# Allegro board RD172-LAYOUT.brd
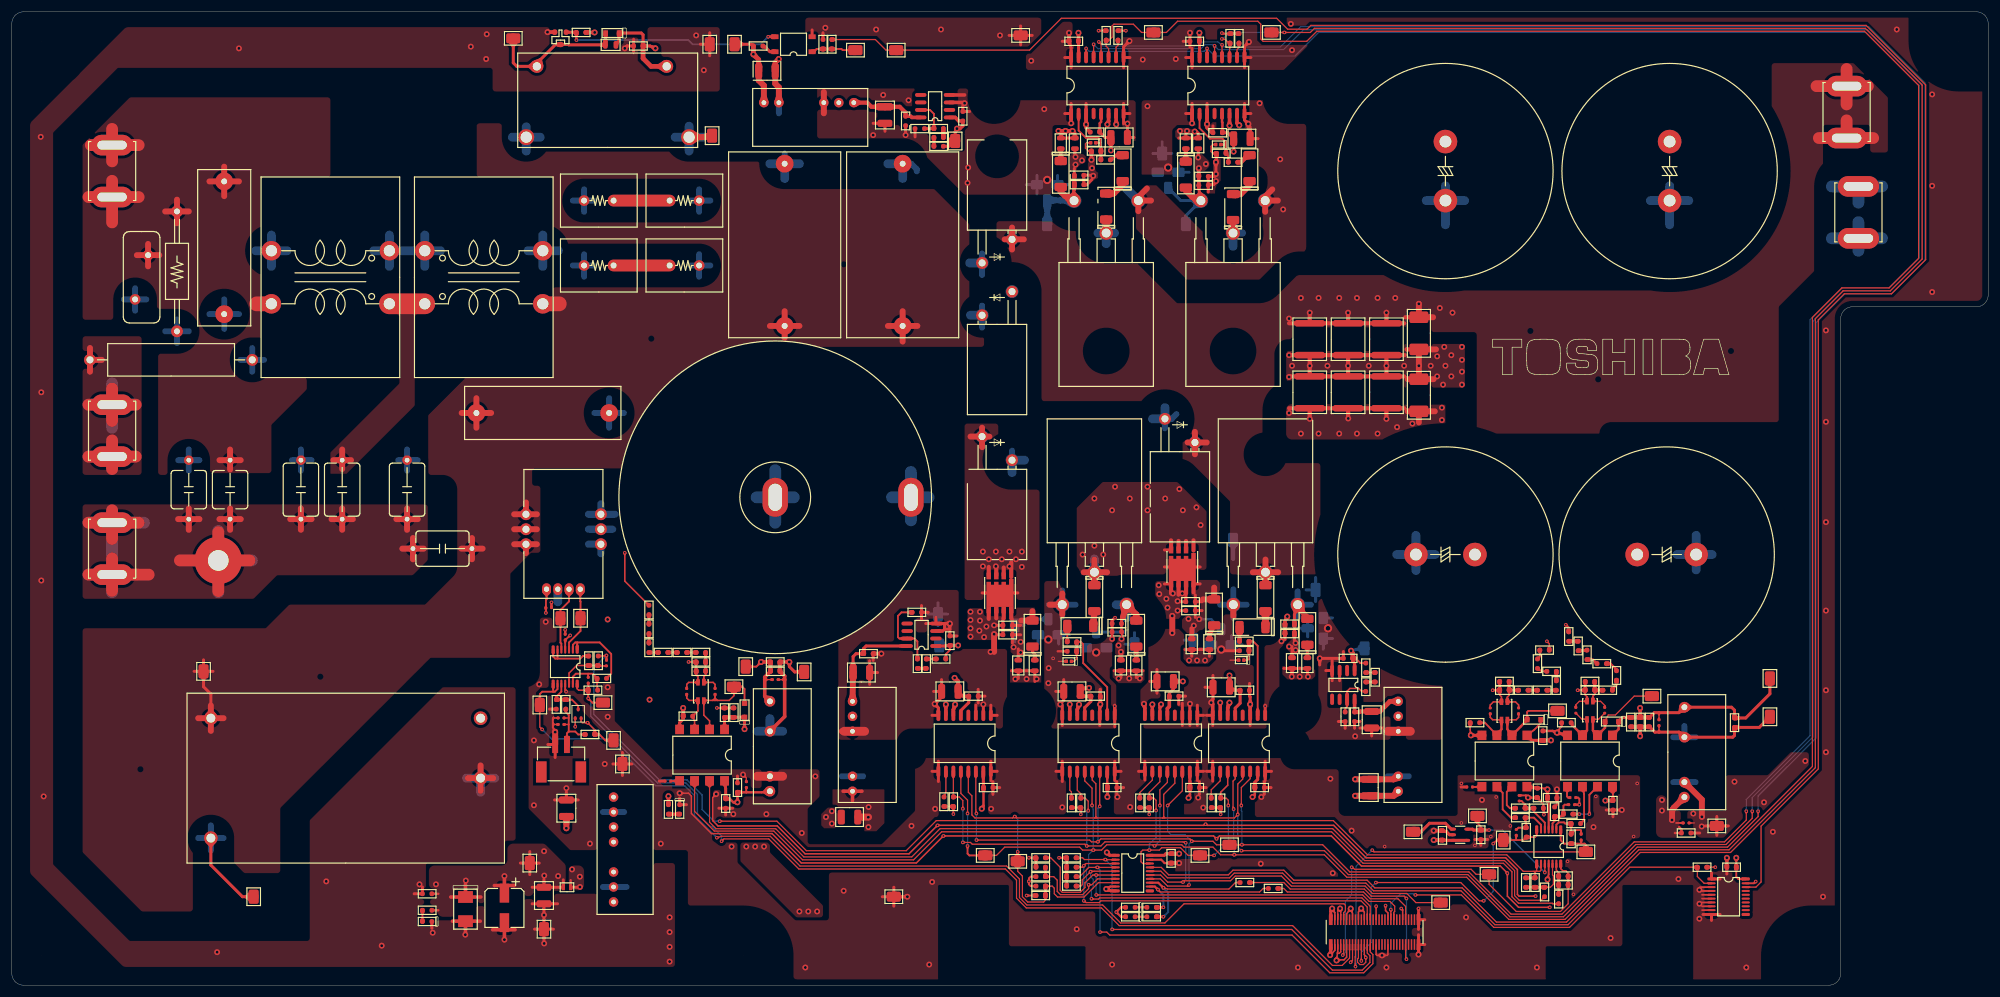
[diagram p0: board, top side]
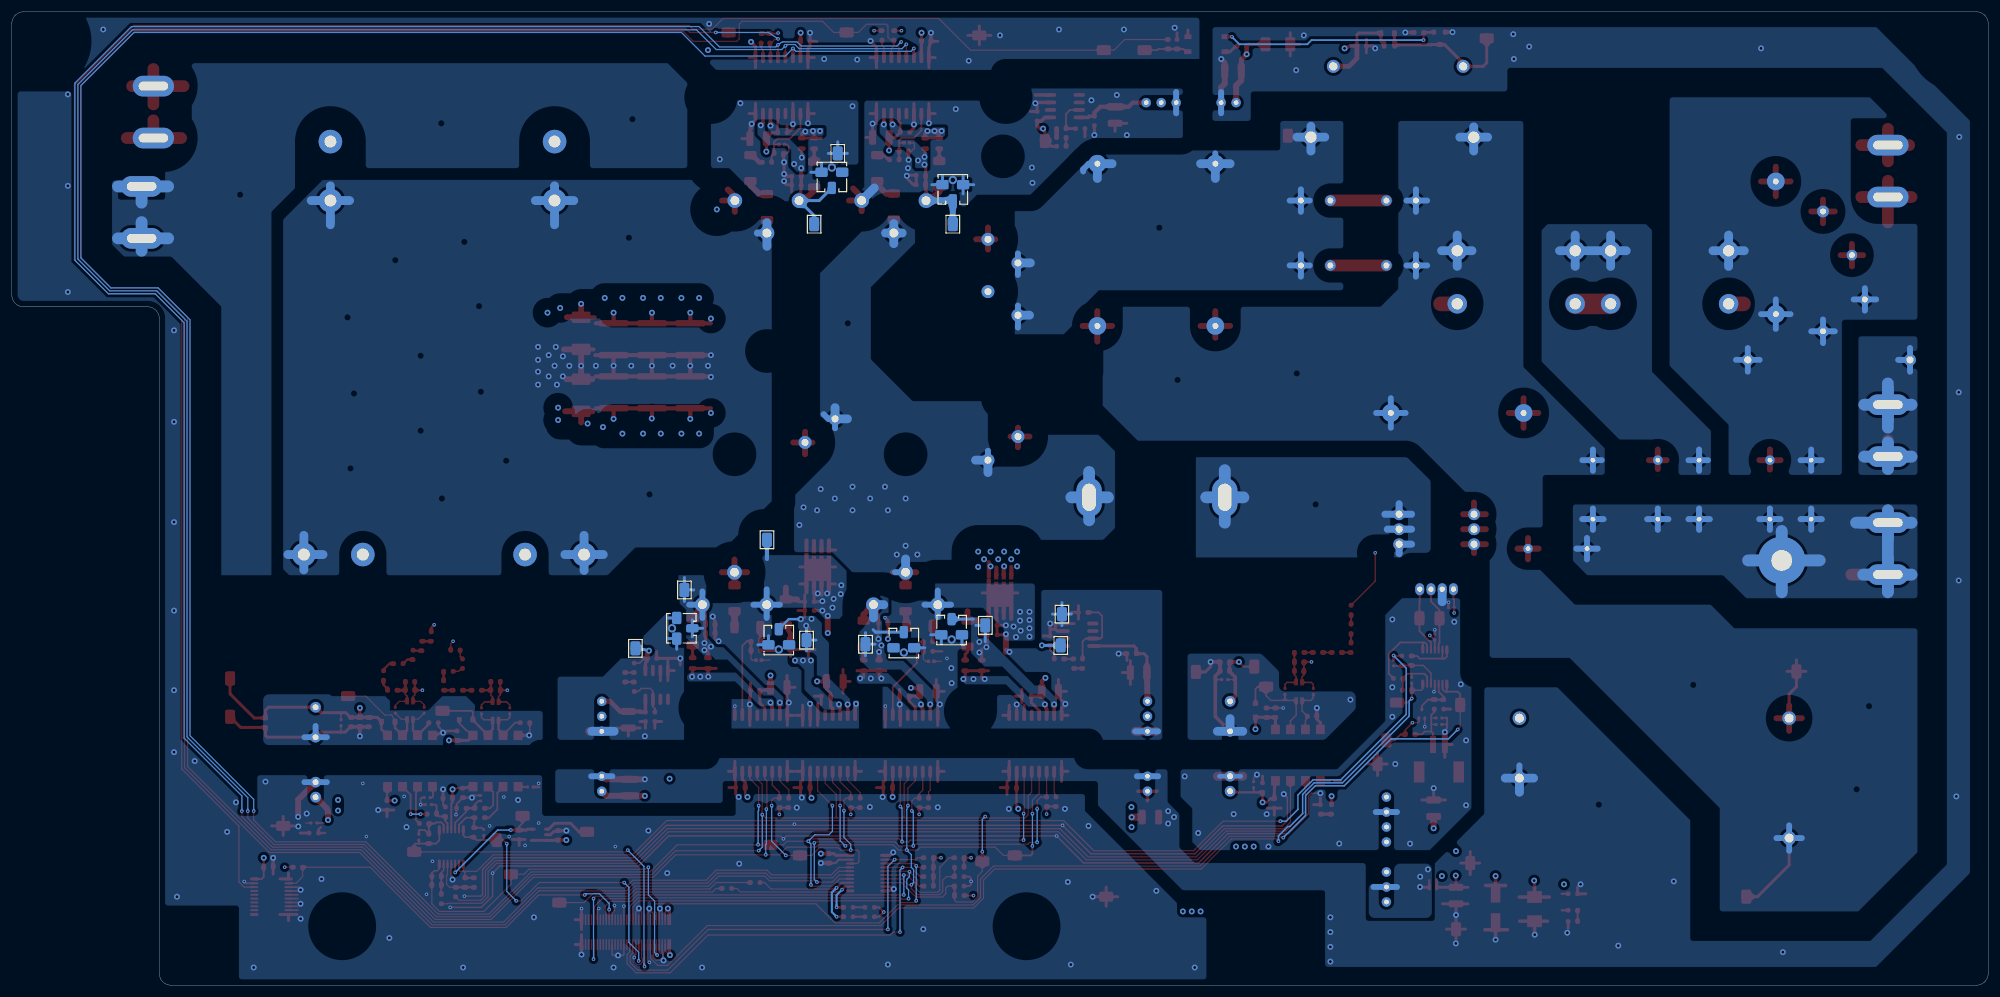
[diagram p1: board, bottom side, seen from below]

Outline 335 x 165 mm; copper layers: TOP, CONDUCTIVE2, CONDUCTIVE3, BOTTOM. Coordinates in mm from the lower left corner of the outline.
Outline path: 0,163 0.03,163.35 0.12,163.68 0.27,164 0.47,164.29 0.71,164.53 1,164.73 1.32,164.88 1.65,164.97 2,165 333,165 333.35,164.97 333.68,164.88 334,164.73 334.29,164.53 334.53,164.29 334.73,164 334.88,163.68 334.97,163.35 335,163 335,117 334.97,116.65 334.88,116.32 334.73,116 334.53,115.71 334.29,115.47 334,115.27 333.68,115.12 333.35,115.03 333,115 312,115 311.65,114.97 311.32,114.88 311,114.73 310.71,114.53 310.47,114.29 310.27,114 310.12,113.68 310.03,113.35 310,113 310,2 309.97,1.65 309.88,1.32 309.73,1 309.53,0.71 309.29,0.47 309,0.27 308.68,0.12 308.35,0.03 308,0 2,0 1.65,0.03 1.32,0.12 1,0.27 0.71,0.47 0.47,0.71 0.27,1 0.12,1.32 0.03,1.65 0,2 0,163

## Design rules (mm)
constraint set DEFAULT: 

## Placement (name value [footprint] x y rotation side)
C2  -  [_C_D_E22_5D0_8W9H18L_1]  36 125 90 top
C3  -  [_C_D_E22_5D0_8W9H18L_1]  90 97 180 top
C4  -  [C_S_1608]  106.2 159.2 180 top
C6  -  [_C_D_E27_5D0_8W19_0H_1]  151 125.5 270 top
C7  -  [_C_D_E27_5D0_8W19_0H_1]  131 125.5 270 top
C8  -  [C_D_10_0_CD45_D9_0_T_1]  49 84 270 top
C9  -  [C_D_10_0_CD45_D9_0_T_1]  56 84 270 top
C10  -  [C_S_1608]  70.4 15.5 180 top
C11  -  [CA_S_D6_3_L7_7_D8_PA_1]  83.5 13.1 270 top
C14  -  [C_S_1608]  211.5 33.5 0 top
C15  -  [C_S_3225]  205 50.5 180 top
C16  -  [C_S_1608]  209 50 0 top
C17  -  [C_S_3225]  230 33.5 90 top
C18  -  [C_S_3225]  230.5 45 270 top
C19  -  [C_S_1608]  227.6 45.5 270 top
C20  -  [C_S_1608]  208.9 56.7 180 top
C21  -  [C_S_1608]  226.5 55.4 180 top
C22  -  [C_S_1608]  216.6 61.2 180 top
C23  -  [C_S_1608]  200.5 33.5 0 top
C24  -  [C_S_3225]  195.5 51.5 180 top
C25  -  [C_S_1608]  197 49 0 top
C26  -  [C_S_1608]  199.8 65 0 top
C31  -  [C_S_1608]  186.5 33.5 0 top
C32  -  [C_S_3225]  179.7 49.8 180 top
C33  -  [C_S_1608]  183.7 49 0 top
C34  -  [C_S_1608]  187.3 61.3 180 top
C35  -  [C_S_3225]  142 28.5 180 top
C36  -  [C_S_3225]  144 53 0 top
C37  -  [C_S_1608]  145.2 56.2 0 top
C38  -  [C_S_1608]  159 58.4 90 top
C39  -  [C_S_1608]  179.7 56.6 180 top
C40  -  [C_S_1608]  165.5 33.5 0 top
C41  -  [C_S_3225]  159 49.8 180 top
C42  -  [C_S_1608]  163 49 0 top
C43  -  [C_S_1608]  168.8 61 0 top
C48  -  [CA_D_D35_L35_P10_CE6_1]  243 138 270 top
C49  -  [CA_D_D35_L35_P10_CE6_1]  281 138 270 top
C50  -  [C_S_3225]  128 155 0 top
C51  -  [C_S_3225]  148 147.5 270 top
C52  -  [C_S_1608]  151.5 146.5 270 top
C53  -  [C_S_1608]  161.2 147.3 90 top
C54  -  [CA_D_D35_L35_P10_CE6_1]  243 73 0 top
C55  -  [CA_D_D35_L35_P10_CE6_1]  280.5 73 180 top
C56  -  [C_S_1608]  180 160 180 top
C57  -  [C_S_3225]  187.7 143.7 0 top
C58  -  [C_S_1608]  183.6 144.6 180 top
C59  -  [C_S_1608]  180.9 135.7 0 top
C60  -  [C_S_1608]  183.8 141.4 180 top
C65  -  [C_S_1608]  200.5 160 180 top
C66  -  [C_S_3225]  208.5 143.5 0 top
C67  -  [C_S_1608]  204.4 144.5 180 top
C68  -  [C_S_1608]  202 135.6 180 top
C69  -  [C_S_1608]  205 141 180 top
C70  -  [C_S_1005]  97.7 51.7 270 top
C71  -  [C_S_1005]  91 64 0 top
C72  -  [C_S_1005]  93.8 59 90 top
C73  -  [C_S_1005]  100.8 54.6 90 top
C74  -  [C_S_1608]  92.3 47.6 270 top
C75  -  [C_S_1005]  93.1 45.3 180 top
C76  -  [C_S_3225]  90.2 15.2 270 top
C77  -  [C_S_3225]  94 30 90 top
C78  -  [C_S_1608]  249 25.5 270 top
C79  -  [C_S_1608]  242.5 25.4 90 top
C80  -  [C_S_1608]  129.4 53.2 0 top
C81  -  [C_S_1608]  129.4 54.8 0 top
C82  -  [C_S_1005]  129.4 51.8 0 top
C83  -  [C_S_1005]  124.5 34 90 top
C84  -  [C_S_1608]  123 33.5 90 top
C85  -  [C_S_1608]  120.8 46.2 90 top
C86  -  [C_S_1608]  121 30.8 270 top
C87  -  [C_S_1608]  116.8 54.8 180 top
C88  -  [C_S_1608]  263 18.5 0 top
C89  -  [C_S_1608]  256.6 17.4 270 top
C90  -  [C_S_1608]  274.4 44.6 270 top
C91  -  [C_S_1608]  271.4 30.5 270 top
C92  -  [C_S_1608]  261.1 31.8 0 top
C93  -  [C_S_1608]  267.5 50 180 top
C94  -  [C_S_1005]  266 25.1 270 top
C95  -  [C_S_1005]  264.4 30.6 180 top
C96  -  [C_S_1608]  259.5 42.3 90 top
C97  -  [C_S_1005]  255 25.9 270 top
C98  -  [C_S_1608]  258.6 32.6 270 top
C99  -  [C_S_1608]  253 50 180 top
C100  -  [C_S_1005]  255.5 31.7 270 top
C101  -  [C_S_1608]  276 44.6 270 top
C102  -  [C_S_1608]  277.6 44.6 270 top
C103  -  [C_S_1005]  279.2 44.5 270 top
C104  -  [C_S_1005]  283.8 27.5 0 top
C105  -  [C_S_1608]  283.8 25.8 0 top
C106  -  [C_S_1608]  196.5 21.5 270 top
C107  -  [C_S_1608]  174.4 18.4 180 top
C108  -  [C_S_1608]  174.4 16.8 180 top
C109  -  [C_S_1608]  291.5 20 180 top
C110  -  [C_S_5750_T2_5]  220 109.5 270 top
C111  -  [C_S_5750_T2_5]  220 100.5 270 top
C112  -  [C_S_5750_T2_5]  233 109.5 270 top
C113  -  [C_S_5750_T2_5]  233 100.5 270 top
C114  -  [C_S_5750_T2_5]  226.5 109.5 270 top
C115  -  [C_S_5750_T2_5]  226.5 100.5 270 top
C120  -  [C_D_10_0_CD45_D9_0_T_1]  67 84 270 top
C121  -  [C_D_10_0_CD45_D9_0_T_1]  73 74 180 top
C122  -  [_C_D_10_0_CD45_D6_5__1]  30 84 270 top
C123  -  [_C_D_10_0_CD45_D6_5__1]  37 84 270 top
CAM1  -  [_TH3_5_8_0]  35 72 0 top
CN1  -  [CN_S_6_1460820_X]  221.5 60.5 180 bottom
CN2  -  [CN_S_6_1460820_X]  205 58.5 90 bottom
CN3  -  [CN_S_6_1460820_X]  183.8 58 90 bottom
CN4  -  [CN_S_6_1460820_X]  175.7 60.2 90 bottom
CN5  -  [CN_S_6_1460820_X]  175.5 134.9 270 bottom
CN6  -  [CN_S_6_1460820_X]  196 137 270 bottom
CN7  -  [CN_S_BM02B_PASS_TFT__1]  93.1 37.5 0 top
CN8  -  [CN_S_WR_60S_VFH05_N1]  231 9 0 top
CT1  -  [_CT_D_F02PXXXS05L_PI_1]  93.5 76.5 90 top
D2  -  [D_S_1_1E1A_USC_AC]  101.8 161.4 0 top
D4  -  [_D_S_M_FLAT_3_4E1A_A_1]  210.3 60.7 0 top
D5  -  [_D_S_M_FLAT_3_4E1A_A_1]  219.6 59.9 270 top
D6  -  [_D_D_TO_220_2L_2_10A_1]  198 92 180 top
D7  -  [_D_D_TO_220_2L_2_10A_1#2]  167 126.43 0 top
D8  -  [_D_S_SOD_882_CST2_1__1]  208.4 55.1 0 top
D9  -  [_D_S_M_FLAT_3_4E1A_A_1]  203.8 63.2 270 top
D10  -  [_D_S_M_FLAT_3_4E1A_A_1]  181.1 60.9 0 top
D11  -  [_D_S_M_FLAT_3_4E1A_A_1]  190.6 59.6 270 top
D12  -  [_D_D_TO_220_2L_2_10A_1#2]  167 113.57 180 top
D13  -  [_D_S_SOD_882_CST2_1__1]  179.18 54.9 0 top
D14  -  [_D_D_TO_220_2L_2_10A_1]  167 89 180 top
D15  -  [_D_S_M_FLAT_3_4E1A_A_1]  173 59.6 270 top
D16  -  [_D_S_M_FLAT_3_4E1A_A_1]  188.3 138.5 270 top
D17  -  [_D_S_M_FLAT_3_4E1A_A_1]  177.8 137.5 90 top
D18  -  [_D_S_SOD_882_CST2_1__1]  183.3 142.8 0 top
D19  -  [_D_S_M_FLAT_3_4E1A_A_1]  199 137.4 90 top
D20  -  [_D_S_SOD_882_CST2_1__1]  204.5 142.5 0 top
D21  -  [_D_S_M_FLAT_3_4E1A_A_1]  209.8 138.5 270 top
D22  -  [_D_S_EMD3_SOT_416_SC_1]  96 46 90 top
D23  -  [D_S_1_1E1A_USC_AC]  124.2 46.6 270 top
D24  -  [D_S_1_1E1A_USC_AC]  271.2 44.7 0 top
D25  -  [D_S_1_1E1A_USC_AC]  258 45 0 top
D26  -  [_D_S_M_FLAT_3_4E1A_A_1]  212.5 65.6 90 top
D27  -  [_D_S_M_FLAT_3_4E1A_A_1]  183.5 65.6 90 top
D28  -  [_D_S_M_FLAT_3_4E1A_A_1]  185.5 132 270 top
D29  -  [_D_S_M_FLAT_3_4E1A_A_1]  207 131.9 270 top
F1  -  [F_D_0487008_016MXEP]  27 106 0 top
IC1  -  [IC_SOP16_1_27_DW_R_P_1]  208 41 180 top
IC2  -  [IC_SOP8_1_27_D]  225.7 50.9 180 top
IC3  -  [IC_SOP16_1_27_DW_R_P_1]  196.5 41 180 top
IC5  -  [IC_SOP16_1_27_DW_R_P_1]  182.5 41 180 top
IC6  -  [IC_SOP8_1_27_D]  154.2 59.4 90 top
IC7  -  [IC_SOP16_1_27_DW_R_P_1]  161.5 41 180 top
IC9  -  [IC_SOP8_1_27_D]  156.5 149 90 top
IC10  -  [IC_SOP16_1_27_DW_R_P_1]  184 152.5 0 top
IC12  -  [IC_SOP16_1_27_DW_R_P_1]  204.5 152.5 0 top
IC13  -  [IC_SOP14_0_65_PW]  93.8 54 180 top
IC14  -  [_IC_SOP5_P_0_95_DDC]  245.5 25.5 180 top
IC15  -  [IC_SOP8_2_54_11_10C4_1]  117 39 180 top
IC16  -  [IC_SOP8_2_54_11_10C4_1]  267.5 38 180 top
IC17  -  [IC_SOP14_0_65_PW]  260.5 23.5 180 top
IC18  -  [IC_SOP8_2_54_11_10C4_1]  253 38 180 top
IC19  -  [IC_SOP20_0_65_FT]  190 19 270 top
IC20  -  [IC_SOP20_0_65_FT]  291 15 270 top
L1  -  [L_D_LDFL011742VV_V0E]  54 120 90 top
L2  -  [L_D_LDFL011742VV_V0E]  80 120 270 top
L3  -  [L_D_TXN40H_10221]  129.4 82.7 0 top
L4  -  [L_S_MBKK1608]  94.1 16.6 0 top
L5  -  [L_S_ACT1210]  116.8 49.8 270 top
L6  -  [L_S_ACT1210]  267.5 46.6 270 top
L7  -  [L_S_ACT1210]  253 46.5 270 top
L8  -  [L_S_LQW15]  111.2 34.6 0 top
L9  -  [L_S_LQW15]  264.6 31.8 180 top
L10  -  [L_S_LQW15]  247.1 33.6 0 top
LED1  -  [LED_S_1608_AC]  70.4 10.8 0 top
LED3  -  [LED_S_1608_AC]  113.2 29.8 90 top
LED4  -  [LED_S_1608_AC]  189.6 11.6 0 top
LED5  -  [LED_S_1608_AC]  189.6 13.2 0 top
NOREF  -  [unnamed]  5 160 0 top
NOREF#2  -  [#2]  117.2 103.7 0 top
NOREF#3  -  [#2]  296.2 135.8 0 top
NOREF#4  -  [#2]  229.8 146.8 0 top
NOREF#5  -  [#2]  137.4 102.6 0 top
NOREF#6  -  [#2]  251.2 88.9 0 top
NOREF#7  -  [#2]  193.3 112.2 0 top
NOREF#8  -  [#2]  261.6 77.8 0 top
NOREF#9  -  [#2]  41.1 35.1 0 top
NOREF#10  -  [#2]  270 122.9 0 top
NOREF#11  -  [#2]  21.8 36.6 0 top
NOREF#12  -  [#2]  118.3 102.5 0 top
NOREF#13  -  [#2]  291.4 107.5 0 top
NOREF#14  -  [#2]  262.1 82.5 0 top
NOREF#15  -  [#2]  22.4 34.5 0 top
NOREF#16  -  [#2]  89.8 90 0 top
NOREF#17  -  [#2]  271.3 98.8 0 top
NOREF#18  -  [#2]  50 50.9 0 top
NOREF#19  -  [#2]  229.1 138.8 0 top
NOREF#20  -  [#2]  258.9 103.1 0 top
NOREF#21  -  [#2]  108.4 109.6 0 top
NOREF#22  -  [#2]  22.3 33.2 0 top
NOREF#23  -  [unnamed]  330 160 0 top
NOREF#24  -  [unnamed]  5 5 0 top
NOREF#25  -  [#2]  296.3 134 0 top
NOREF#26  -  [#2]  261.1 116.1 0 top
NOREF#27  -  [#2]  226.9 83.2 0 top
NOREF#28  -  [unnamed]  305 5 0 top
NOREF#29  -  [#2]  139.2 99.2 0 top
NOREF#30  -  [#2]  265.7 106.7 0 top
NOREF#31  -  [#2]  113.6 84.1 0 top
NOREF#32  -  [#2]  257.4 110.9 0 top
NOREF#33  -  [#2]  268.9 102.7 0 top
NOREF#34  -  [#2]  277 100.3 0 top
NOREF#35  -  [#2]  278.1 113.2 0 top
NOREF#36  -  [#2]  50.1 49.9 0 top
NOREF#37  -  [#2]  52.3 52.3 0 top
NOREF#38  -  [#2]  255.8 115.1 0 top
NOREF#39  -  [#2]  255.5 100.6 0 top
NOREF#40  -  [#2]  114 81.5 0 top
NOREF#41  -  [#2]  283.7 103.2 0 top
NOREF#42  -  [#2]  262 129.4 0 top
NOREF#43  -  [unnamed#3]  191.5 95.5 0 top
NOREF#44  -  [#2]  261.7 142.7 0 top
NOREF#45  -  [#2]  258.3 126 0 top
NOREF#46  -  [#2]  141 122.2 0 top
NOREF#47  -  [#2]  285.5 116.5 0 top
NOREF#48  -  [#2]  225.3 80.9 0 top
NOREF#49  -  [#2]  230.4 126.7 0 top
NOREF#50  -  [unnamed]  124 5 0 top
NOREF#51  -  [#2]  140.5 128.4 0 top
NOREF#52  -  [#2]  265.7 94 0 top
NOREF#53  -  [#2]  273.2 111.3 0 top
NOREF#54  -  [#2]  277.6 87.6 0 top
NOREF#55  -  [#2]  139.3 128.5 0 top
NOREF#56  -  [#2]  261.4 90.4 0 top
NOREF#57  -  [#2]  262.2 146.1 0 top
NOREF#58  -  [#2]  250.1 84.7 0 top
NOREF#59  -  [unnamed#4]  231 9 180 top
NOREF#60  -  [unnamed]  154 104 0 top
NOREF#61  -  [#2]  281.5 90.6 0 top
NOREF#62  -  [#2]  66 30.6 0 top
NOREF#63  -  [#2]  20.2 47.3 0 top
NOREF#64  -  [#2]  251 103.5 0 top
PC2  -  [IC_SOP4_2_54_11_4M1S]  132.5 159.5 90 top
PS1  -  [IC_D_PSK_S10C]  56.6 35.1 0 top
PS3  -  [IC_D_RXXPXXS_D_R_SER_1]  235 40.5 90 top
PS5  -  [IC_D_RXXPXXS_D_R_SER_1]  142.5 40.5 90 top
PS7  -  [IC_D_RXXPXXS_D_R_SER_1]  135.1 149.6 0 top
PS9  -  [_IC_D_MGFS10_COSEL_P_1]  102 23 90 top
PS10  -  [IC_D_HXXXXS_1WR2_2WR_1]  128.5 40.5 90 top
PS11  -  [IC_D_HXXXXS_1WR2_2WR_1]  283.5 39.5 90 top
Q2  -  [Q_S_SOT_23F_GSD]  93 160.5 180 top
Q3  -  [_Q_D_TO_247_3_GDS_SP_1]  212.5 85.5 0 top
Q4  -  [_Q_S_SOP_ADVANCE_GDS]  198.4 70.9 0 top
Q5  -  [_Q_D_TO_247_3_GDS_SP_1]  183.5 85.5 0 top
Q6  -  [_Q_S_SOP_ADVANCE_GDS]  167.5 66.5 0 top
Q7  -  [_Q_D_TO_247_3_GDS_SP_1]  185.5 112 180 top
Q8  -  [_Q_D_TO_247_3_GDS_SP_1]  207 112 180 top
R1  -  [_R_D_SQMW5]  99.5 133 0 top
R2  -  [_R_D_SQMW5]  99.5 122 0 top
R3  -  [R_D_RCR60_9_5X3_5]  28 121 270 top
R4  -  [_R_D_SQMW5]  114 133 0 top
R5  -  [_R_D_SQMW5]  114 122 0 top
R11  -  [R_S_1608]  70.4 12.7 180 top
R12  -  [R_S_2012]  101.5 159.4 180 top
R13  -  [R_S_1608]  126.5 159.2 180 top
R14  -  [R_S_1608]  139 159.5 270 top
R15  -  [R_S_1608]  137.5 159.5 90 top
R17  -  [R_S_1608]  96.5 161.5 180 top
R18  -  [R_S_1608]  208.9 58.3 180 top
R19  -  [R_S_1608]  204.9 30.9 270 top
R20  -  [R_S_1608]  203.3 30.9 270 top
R21  -  [R_S_2012]  217 54.6 90 top
R22  -  [R_S_1608]  229.5 53.8 90 top
R23  -  [R_S_2012]  219.6 54.6 90 top
R24  -  [R_S_1608]  231.1 52.2 270 top
R25  -  [R_S_1608]  229.5 50.6 90 top
R26  -  [R_S_1608]  216.6 59.6 0 top
R27  -  [R_S_1608]  226 45.5 90 top
R28  -  [R_S_1608]  192.8 30.9 270 top
R29  -  [R_S_1608]  191.2 30.9 270 top
R30  -  [R_S_1608]  199.8 63.5 180 top
R31  -  [R_S_2012]  200 57.8 90 top
R32  -  [R_S_2012]  203 57.8 90 top
R37  -  [R_S_1608]  179.7 58.2 180 top
R38  -  [R_S_1608]  181.2 30.9 270 top
R39  -  [R_S_1608]  179.6 30.9 270 top
R40  -  [R_S_2012]  188 54.2 90 top
R41  -  [R_S_2012]  190.6 54.2 90 top
R42  -  [R_S_1608]  187.3 59.9 0 top
R43  -  [R_S_1608]  157.51 55.3 0 top
R44  -  [R_S_1608]  155 54.5 270 top
R45  -  [R_S_1608]  153.5 54.5 270 top
R46  -  [R_S_1608]  153.4 63.2 180 top
R47  -  [R_S_1608]  159.6 31.1 270 top
R48  -  [R_S_1608]  158 31.1 270 top
R49  -  [R_S_1608]  168.8 59.4 180 top
R50  -  [R_S_2012]  170.6 54.2 90 top
R51  -  [R_S_2012]  173.4 54.2 90 top
R56  -  [R_S_6432_T1_25]  238.5 110.5 90 top
R57  -  [R_S_1608]  157.1 142.2 0 top
R58  -  [R_S_1608]  157.1 143.7 0 top
R59  -  [R_S_1608]  157.1 145.2 0 top
R60  -  [R_S_1608]  153.9 145.2 0 top
R61  -  [R_S_6432_T1_25]  238.5 100 90 top
R62  -  [R_S_1608]  185.5 161 90 top
R63  -  [R_S_1608]  187.5 161 90 top
R64  -  [R_S_1608]  185.4 139.9 0 top
R65  -  [R_S_2012]  180.2 142.7 270 top
R66  -  [R_S_2012]  177.8 142.7 270 top
R67  -  [R_S_1608]  180.9 137.3 180 top
R72  -  [R_S_1608]  206.5 160.5 90 top
R73  -  [R_S_1608]  208 160.5 90 top
R74  -  [R_S_1608]  202 137.1 0 top
R75  -  [R_S_2012]  201.1 142.7 270 top
R76  -  [R_S_2012]  199 142.7 270 top
R77  -  [R_S_1608]  207 139.5 0 top
R78  -  [R_S_1608]  100 52 180 top
R79  -  [R_S_1608]  98.5 50 180 top
R80  -  [R_S_1608]  97.8 55 270 top
R81  -  [R_S_1608]  99.4 55 90 top
R82  -  [R_S_1608]  98 42.5 0 top
R83  -  [R_S_1608]  93.9 47.6 270 top
R84  -  [R_S_1005]  93.1 44.2 0 top
R85  -  [R_S_1608]  111.3 29.8 270 top
R86  -  [R_S_1608]  122.4 46.2 270 top
R87  -  [R_S_1005]  119.2 49.8 270 top
R88  -  [R_S_1608]  108 63.6 270 top
R89  -  [R_S_1608]  108 60.4 270 top
R90  -  [R_S_1608]  108 57.2 270 top
R91  -  [R_S_1608]  110.4 56.4 0 top
R92  -  [R_S_1608]  113.6 56.4 0 top
R93  -  [R_S_1608]  116.8 56.4 0 top
R94  -  [R_S_1608]  116.8 53.2 0 top
R95  -  [R_S_1608]  262.2 14.6 90 top
R96  -  [R_S_1608]  263 17 0 top
R97  -  [R_S_1608]  114.6 45.6 180 top
R98  -  [R_S_1608]  259.8 15.8 90 top
R99  -  [R_S_1608]  258.2 17.4 270 top
R100  -  [R_S_1005]  114.4 49.8 270 top
R101  -  [R_S_1005]  270 46.6 270 top
R102  -  [R_S_1608]  263.9 59.1 270 top
R103  -  [R_S_1608]  267 56 270 top
R104  -  [R_S_1608]  269.5 54.5 0 top
R105  -  [R_S_1608]  272 52.5 270 top
R106  -  [R_S_1608]  270.5 50 180 top
R107  -  [R_S_1608]  265.1 27.4 180 top
R108  -  [R_S_1608]  264.3 24.8 270 top
R109  -  [R_S_1608]  265.5 57.5 270 top
R110  -  [R_S_1608]  267.5 51.5 0 top
R111  -  [R_S_1608]  263.5 44.5 180 top
R112  -  [R_S_1608]  263.8 29 180 top
R113  -  [R_S_1608]  261.5 29.41 270 top
R114  -  [R_S_1005]  265.1 46.6 270 top
R115  -  [R_S_1005]  255.4 46.5 270 top
R116  -  [R_S_1608]  255.7 30 0 top
R117  -  [R_S_1608]  259.8 56.8 180 top
R118  -  [R_S_1608]  258.6 54.5 270 top
R119  -  [R_S_1608]  261 53.2 0 top
R120  -  [R_S_1608]  261.8 50.8 270 top
R121  -  [R_S_1608]  259.4 50 180 top
R122  -  [R_S_1608]  253 51.5 0 top
R123  -  [R_S_1608]  255.7 28.4 0 top
R124  -  [R_S_1608]  256.7 25.9 270 top
R125  -  [R_S_1608]  256.2 50 180 top
R126  -  [R_S_1608]  258.8 30 180 top
R127  -  [R_S_1608]  248 44.5 180 top
R128  -  [R_S_1005]  250.6 46.5 270 top
R129  -  [R_S_1608]  292 44.5 90 top
R130  -  [R_S_1608]  179.6 20 180 top
R131  -  [R_S_1608]  179.6 18.4 180 top
R132  -  [R_S_1608]  179.6 16.8 180 top
R133  -  [R_S_1608]  174.4 21.6 180 top
R134  -  [R_S_1608]  174.4 20 180 top
R135  -  [R_S_1608]  174.4 15.2 180 top
R136  -  [R_S_1608]  179.6 21.6 180 top
R137  -  [R_S_1608]  193.2 11.6 180 top
R138  -  [R_S_1608]  193.2 13.2 180 top
R139  -  [R_S_1608]  209 17.4 0 top
R140  -  [R_S_1608]  213.8 16.4 0 top
R141  -  [R_S_1608]  286.5 20 0 top
RLY2  -  [RL_D_G6QE_1A]  101 150 0 top
TB1  -  [TB_D_OT_264]  17 94 270 top
TB2  -  [TB_D_OT_264]  17 138 270 top
TB3  -  [TB_D_OT_264]  17 74 270 top
TB4  -  [TB_D_OT_264]  311 148 270 top
TB5  -  [TB_D_OT_264]  313 131 270 top
TP2  -  [TP_HK_3_G]  118.7 144 90 top
TP7  -  [TP_HK_3_G]  87.8 20.7 270 top
TP8  -  [TP_HK_3_G]  32.5 53.2 270 top
TP9  -  [TP_HK_3_G]  118.3 159.5 270 top
TP10  -  [TP_HK_3_G]  41 15 90 top
TP11  -  [TP_HK_3_G]  85 160.5 0 top
TP12  -  [TP_HK_3_G]  143 158.5 0 top
TP17  -  [TP_HK_3_G]  229.3 57.1 270 bottom
TP18  -  [TP_HK_3_G]  221 67 90 bottom
TP19  -  [TP_HK_3_G]  207 75.5 90 bottom
TP22  -  [TP_HK_3_G]  200.3 58.5 270 bottom
TP26  -  [TP_HK_3_G]  190.3 57.8 90 bottom
TP27  -  [TP_HK_3_G]  157.2 57.6 270 bottom
TP28  -  [TP_HK_3_G]  157 62.9 90 bottom
TP31  -  [TP_HK_3_G]  170 61 90 bottom
TP33  -  [TP_HK_3_G]  159.9 143.1 90 top
TP36  -  [TP_HK_3_G]  175.5 129 90 bottom
TP37  -  [TP_HK_3_G]  195 141 90 bottom
TP42  -  [TP_HK_3_G]  199 129 90 bottom
TP43  -  [TP_HK_3_G]  149.5 15 180 top
TP44  -  [TP_HK_3_G]  93 62.2 270 top
TP45  -  [TP_HK_3_G]  96.4 62.2 270 top
TP46  -  [TP_HK_3_G]  100.2 47.9 180 top
TP47  -  [TP_HK_3_G]  89.5 47.5 270 top
TP48  -  [TP_HK_3_G]  122.5 159.5 270 top
TP49  -  [TP_HK_3_G]  102 41.5 270 top
TP50  -  [TP_HK_3_G]  103.5 37.5 270 top
TP51  -  [TP_HK_3_G]  248.43 28.7 0 top
TP52  -  [TP_HK_3_G]  237.5 26 0 top
TP53  -  [TP_HK_3_G]  90.2 9.5 270 top
TP54  -  [TP_HK_3_G]  124.4 54 270 top
TP55  -  [TP_HK_3_G]  134.3 53.1 270 top
TP56  -  [TP_HK_3_G]  171 161 0 top
TP57  -  [TP_HK_3_G]  122.4 50.6 0 top
TP58  -  [TP_HK_3_G]  250.4 18.8 0 top
TP59  -  [TP_HK_3_G]  266.8 22.6 0 top
TP60  -  [TP_HK_3_G]  278 49 0 top
TP61  -  [TP_HK_3_G]  262 46.5 0 top
TP62  -  [TP_HK_3_G]  252.8 24.6 270 top
TP63  -  [TP_HK_3_G]  298 52 270 top
TP64  -  [TP_HK_3_G]  298 45.5 270 top
TP65  -  [TP_HK_3_G]  289 27 0 top
TP66  -  [TP_HK_3_G]  165 22 180 top
TP67  -  [TP_HK_3_G]  170.5 21 180 top
TP68  -  [TP_HK_3_G]  201.4 22 180 top
TP69  -  [TP_HK_3_G]  193.5 161.5 0 top
TP70  -  [TP_HK_3_G]  213.5 161.5 0 top
TP71  -  [TP_HK_3_G]  242.2 14 180 top
TP72  -  [TP_HK_3_G]  206.4 23.8 180 top
TP74  -  [TP_HK_3_G]  149.9 158.5 0 top
ZD1  -  [_D_S_SMB_DO_214AA_AC]  76.9 12.9 90 top
ZNR1  -  [_ZNR_D_TND14V_15_5_6_1]  22 120 90 top

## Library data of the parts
C2 C3 = -C-F339X142248MIP2T0
C4 C10 C14 C16 C19 C21 C23 C25 C31 C33 C37 C38 C40 C42 C52 C53 C56 C58 C65 C67 C78 C79 C81 C85 C86 C90-C92 C96 C98 C102 C106 C109 = -C-UMK107AB7105KA-T
C6 C7 = -C-B32914A3225M000
C8 C9 C120 C121 = -C-CD45-E2GA222M-VKA
C11 = -C-EEHZC1V680XP
C15 C17 C18 C24 C32 C35 C36 C41 C50 C51 C57 C66 C76 C77 = -C-UMK325AB7106KM-T
C20 C39 C60 C69 = -C-CGA3E2C0G1H330J080AA
C22 C26 C34 C43 C59 C68 = -C-GRM1885C1H682JA01D
C48 C49 C54 C55 = -C-LGW2E102MELC35
C70 C73 = -C-GCM1555C1H270FA16D
C71 C72 C75 C82 C83 C103 C104 = -C-UMK105BJ104KV-F
C74 C87 C93 C99 = -C-GRM1885C1H102JA01D
C80 C84 C101 C105 = -C-GRM188D71A106KA73D
C88 C89 = -C-GRM1882C1H222JA01D
C94 C95 C97 C100 = -C-GRM1555C1H102JA01D
C107 C108 = -C-NC_C1608
C110-C115 = -C-C5750X6S2W225K250KA
C122 C123 = -C-CD45-B2GA101K-VKA
CAM1 = -TH-TH3.5-8.0
CN1-CN6 = -CN-6-1460820-1
CN7 = -CN-BM02B-PASS-TFT_LF_SN
CN8 = -CN-WR-60S-VFH05-N1
CT1 = -CT-F02P015S05L_PIN
D2 D23-D25 = -D-BAS316_H3F_AC
D4 D10 D16 D21 D26-D29 = -D-CMF05_AC
D5 D9 D11 D15 D17 D19 = -D-CMS04_TE12L_Q_AC
D6 D7 D12 D14 = -D-TRS6E65F_S1Q_AC: alternate symbols: (_D_D_TO_220_2L_2_10A_2)
D8 D13 D18 D20 = -D-1SS417CTL3F_AC
D22 = -D-1SS423_TE85L_F_AC
F1 = -F-0487016MXEP
IC1 IC3 IC5 IC7 IC10 IC12 = -IC-ISO5851DWR
IC2 IC6 IC9 = -IC-LP2951D
IC13 IC17 = -IC-OPA4325IPWR
IC14 = -IC-REF2025AIDDCT
IC15 IC16 IC18 = -IC-TLP7920_LF5_TP5
IC19 = -IC-74VHC541FT
IC20 = -IC-74VHC540FT
L1 L2 = -L-LDFL011742VV-V0E
L3 = -L-TXN40H-10221
L4 = -L-MBKK1608T1R0M
L5-L7 = -L-ACT1210-101-2P-TL00
L8-L10 = -L-LQW15CA22NK00
LED1 LED3 = -LED-VCDG1111C-4BY3C-TR_AC
LED4 LED5 = -LED-VFHR1111C-3BY2A-TR_AC
PC2 = -PC-TLP183_TPL_E
PS1 = -PS-PSK-S10C-24
PS3 PS5 PS7 = -PS-R24P209D
PS9 = -PS-MGFS102405_PIN
PS10 PS11 = -PS-H0505S-1WR2
Q2 = -Q-SSM3K318R_LF
Q3 Q5 = -Q-TK090N65Z
Q4 Q6 = -Q-TPHR9203PL_GDS
Q7 Q8 = -Q-TK62N60W5
R1 R2 R4 R5 = -R-SQMW556RJ
R3 = -R-RCR60C474J
R11 R13 R18 R26 R30 R37 R42 R49 R67 R74 R130-R133 R136 R141 = -R-ERJ3EKF1002V
R12 = -R-RK73B2ATTD103J
R14 = -R-ERJ3EKF3900V
R15 R83 R85 R134 R135 = -R-RK73B1JTTD102J
R17 = -R-RK73B1JTTD392J
R19 R28 R38 R47 R62 R72 = -R-NC_R1608
R20 R29 R39 R48 R63 R73 R97 R104-R106 R111 R127 = -R-RK73Z1JTTD
R21 R31 R40 R50 = -R-RK73H2ATTD1500F
R22 R43 R57 R108 R113 R124 R126 = -R-ERA3ARB823V
R23 R32 R41 R51 R65 R66 R75 R76 = -R-ERJ6DQF3R3V
R24 R25 R44 R45 R58 R59 = -R-ERA3APB623V
R27 R46 R60 = -R-RK73H1JTTD1802F
R56 R61 = -R-352227KFT
R64 R77 = -R-ERJ3EKF1202V
R78 R80 = -R-ERA3AEB103V
R79 R81 = -R-ERA3AEB203V
R82 = -R-ERJ3EKF2201V
R84 = -R-RK73H1ETTP1003F
R86 R129 = -R-RK73B1JTTD473J
R87 R100 R101 R114 R115 R128 = -R-NC_R1005
R88-R93 R102 R103 R109 R117-R121 R125 = -R-ERA3AEB184V
R94 R110 R122 = -R-ERA3AEB431V
R95 R98 R107 R112 R116 R123 = -R-ERA3ARB273V
R96 R99 = -R-ERA3AEB393V
R137 R138 = -R-ERJ3EKF6200V
R139 R140 = -R-ERJ3EKF1000V
RLY2 = -RL-G6QE-1A_DC24
TB1-TB5 = _TB_OT_264
TP2 TP7-TP12 TP17-TP19 TP22 TP26-TP28 TP31 TP33 TP36 TP37 TP42-TP72 TP74 = -TP-HK-3-G
ZD1 = -D-SMBJ30A_AC
ZNR1 = -ZNR-TND14V-471KB00AAA0

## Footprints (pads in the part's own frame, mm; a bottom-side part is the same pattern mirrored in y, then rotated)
_C_D_10_0_CD45_D6_5__1
  round 1.6 hole 0.8: 1(-5,0) 2(5,0)
_C_D_E22_5D0_8W9H18L_1
  round 3 hole 1: 1(-11.25,0) 2(11.25,0)
_C_D_E27_5D0_8W19_0H_1
  round 3 hole 1: 1(-13.75,0) 2(13.75,0)
_CT_D_F02PXXXS05L_PI_1
  round 2 hole 1.2: 1(-1.75,6.35) 2(0.79,6.35) 3(3.33,6.35) 8(3.33,-6.35) 9(0.79,-6.35) 10(-1.75,-6.35)
  oval 2x1.5 hole 0.9: GND(-9.37,0.953) VCC(-9.37,2.857) VO(-9.37,-0.953) VREF(-9.37,-2.857)
_D_D_TO_220_2L_2_10A_1
  round 2 hole 1.2: A(2.54,-4) C(-2.54,0)
_D_D_TO_220_2L_2_10A_1#2
  round 0.01 hole 6.4 unplated: (0,14.07)
  round 2 hole 1.2: A(-2.54,-4) C(2.54,0)
_D_S_EMD3_SOT_416_SC_1
  custom 0.125x0.125 smd: A(-0.75,0.5) C(-0.75,-0.5) C/A(0.75,0)
_D_S_M_FLAT_3_4E1A_A_1
  custom 0.35x0.35 smd: A(-2.2,0) C(2.2,0)
_D_S_SMB_DO_214AA_AC
  rect 2x2.5 smd: A(-2.05,0) C(2.05,0)
_D_S_SOD_882_CST2_1__1
  custom 0.138x0.138 smd: A(-0.425,0) C(0.425,0)
_IC_D_MGFS10_COSEL_P_1
  round 1.6 hole 0.8: +VIN(-6.35,0) +VOUT(3.81,0) -VIN(-8.89,0) -VOUT(6.35,0) NC(1.27,0) NC2(8.89,0) RC(-3.81,0)
_IC_SOP5_P_0_95_DDC
  custom 0.125x0.125 smd: 1(1.2,-0.95) 2(1.2,0) 3(1.2,0.95) 4(-1.2,0.95) 5(-1.2,-0.95)
_Q_D_TO_247_3_GDS_SP_1
  round 0.01 hole 6.4 unplated: (0,4.5)
  round 2.3 hole 1.5: D(0,-15.5) G(5.45,-21) S(-5.45,-21)
_Q_S_SOP_ADVANCE_GDS
  custom 1.14x1.14 smd: D1(0,0)
  rect 0.75x1.15 smd: D2(0.635,2.875) D3(-0.635,2.875) D4(-1.905,2.875) G(1.905,-2.875) S1(-1.905,-2.875) S2(-0.635,-2.875) S3(0.635,-2.875)
_R_D_SQMW5
  round 1.8 hole 1: 1(-2.5,0) 2(2.5,0)
_TH3_5_8_0
  round 8 hole 3.5: 1(0,0)
_ZNR_D_TND14V_15_5_6_1
  round 1.8 hole 1: 1(-3.75,1.1) 2(3.75,-1.1)
C_D_10_0_CD45_D9_0_T_1
  round 1.6 hole 0.8: 1(-5,0) 2(5,0)
C_S_1005
  custom 0.113x0.113 smd: 1(-0.475,0) 2(0.475,0)
C_S_1608
  custom 0.2x0.2 smd: 1(-0.8,0) 2(0.8,0)
C_S_3225
  custom 0.3x0.3 smd: 1(-1.4,0) 2(1.4,0)
C_S_5750_T2_5
  custom 0.275x0.275 smd: 1(-2.7,0) 2(2.7,0)
CA_D_D35_L35_P10_CE6_1
  round 4 hole 2: 1(-5,0) 2(5,0)
CA_S_D6_3_L7_7_D8_PA_1
  rect 3.2x1.6 smd: 1(-2.5,0) 2(2.5,0)
CN_S_6_1460820_X
  custom 0.4x0.4 smd: G1(-0.8,-1.75) G2(-0.8,1.75)
  custom 0.35x0.35 smd: S(1.85,0)
CN_S_BM02B_PASS_TFT__1
  rect 1x2.9 smd: 1(1,3.3) 2(-1,3.3)
  rect 1.8x3.6 smd: NC1(3.35,-1.35) NC2(-3.35,-1.35)
CN_S_WR_60S_VFH05_N1
  custom 0.156x0.156 smd: 1(-7.438,-2.1) 2(-7.438,2.1) 59(7.438,-2.1) 60(7.438,2.1)
  rect 0.25x1.8 smd: 3(-6.75,-2.1) 4(-6.75,2.1) 5(-6.25,-2.1) 6(-6.25,2.1) 7(-5.75,-2.1) 8(-5.75,2.1) 9(-5.25,-2.1) 10(-5.25,2.1) 11(-4.75,-2.1) 12(-4.75,2.1) 13(-4.25,-2.1) 14(-4.25,2.1) 15(-3.75,-2.1) 16(-3.75,2.1) 17(-3.25,-2.1) 18(-3.25,2.1) 19(-2.75,-2.1) 20(-2.75,2.1) 21(-2.25,-2.1) 22(-2.25,2.1) 23(-1.75,-2.1) 24(-1.75,2.1) 25(-1.25,-2.1) 26(-1.25,2.1) 27(-0.75,-2.1) 28(-0.75,2.1) 29(-0.25,-2.1) 30(-0.25,2.1) 31(0.25,-2.1) 32(0.25,2.1) 33(0.75,-2.1) 34(0.75,2.1) 35(1.25,-2.1) 36(1.25,2.1) 37(1.75,-2.1) 38(1.75,2.1) 39(2.25,-2.1) 40(2.25,2.1) 41(2.75,-2.1) 42(2.75,2.1) 43(3.25,-2.1) 44(3.25,2.1) 45(3.75,-2.1) 46(3.75,2.1) 47(4.25,-2.1) 48(4.25,2.1) 49(4.75,-2.1) 50(4.75,2.1) 51(5.25,-2.1) 52(5.25,2.1) 53(5.75,-2.1) 54(5.75,2.1) 55(6.25,-2.1) 56(6.25,2.1) 57(6.75,-2.1) 58(6.75,2.1)
D_S_1_1E1A_USC_AC
  rect 0.8x0.9 smd: A(-1.15,0) C(1.15,0)
F_D_0487008_016MXEP
  round 2 hole 1.2: 1(-13.75,0) 2(13.75,0)
IC_D_HXXXXS_1WR2_2WR_1
  round 1.8 hole 1: 1(-7.62,0) 2(-5.08,0) 5(2.54,0) 7(7.62,0)
IC_D_PSK_S10C
  round 2.3 hole 1.5: 1(-22.86,10.16) 2(-22.86,-10.16) 3(22.86,0) 4(22.86,10.16)
IC_D_RXXPXXS_D_R_SER_1
  round 1.6 hole 0.8: 1(-7.62,0) 2(-5.08,0) 5(2.54,0) 6(5.08,0) 7(7.62,0)
IC_SOP4_2_54_11_4M1S
  rect 0.8x1.2 smd: 1(-1.27,-3.15) 3(1.27,-3.15) 4(1.27,3.15) 6(-1.27,3.15)
IC_SOP8_1_27_D
  custom 0.163x0.163 smd: 1(-1.905,-2.435) 2(-0.635,-2.435) 3(0.635,-2.435) 4(1.905,-2.435) 5(1.905,2.435) 6(0.635,2.435) 7(-0.635,2.435) 8(-1.905,2.435)
IC_SOP8_2_54_11_10C4_1
  rect 1.5x1.6 smd: 1(-3.81,-4.35) 2(-1.27,-4.35) 3(1.27,-4.35) 4(3.81,-4.35) 5(3.81,4.35) 6(1.27,4.35) 7(-1.27,4.35) 8(-3.81,4.35)
IC_SOP14_0_65_PW
  custom 0.131x0.131 smd: 1(-2.038,-2.9) 7(2.038,-2.9) 8(2.038,2.9) 14(-2.038,2.9)
  custom 0.087x0.087 smd: 2(-1.3,-2.9) 3(-0.65,-2.9) 4(0,-2.9) 5(0.65,-2.9) 6(1.3,-2.9) 9(1.3,2.9) 10(0.65,2.9) 11(0,2.9) 12(-0.65,2.9) 13(-1.3,2.9)
IC_SOP16_1_27_DW_R_P_1
  custom 0.163x0.163 smd: 1(-4.445,-4.745) 2(-3.175,-4.745) 3(-1.905,-4.745) 4(-0.635,-4.745) 5(0.635,-4.745) 6(1.905,-4.745) 7(3.175,-4.745) 8(4.445,-4.745) 9(4.445,4.745) 10(3.175,4.745) 11(1.905,4.745) 12(0.635,4.745) 13(-0.635,4.745) 14(-1.905,4.745) 15(-3.175,4.745) 16(-4.445,4.745)
IC_SOP20_0_65_FT
  custom 0.131x0.131 smd: 1(-3.013,-2.9) 10(3.013,-2.9) 11(3.013,2.9) 20(-3.013,2.9)
  custom 0.087x0.087 smd: 2(-2.275,-2.9) 3(-1.625,-2.9) 4(-0.975,-2.9) 5(-0.325,-2.9) 6(0.325,-2.9) 7(0.975,-2.9) 8(1.625,-2.9) 9(2.275,-2.9) 12(2.275,2.9) 13(1.625,2.9) 14(0.975,2.9) 15(0.325,2.9) 16(-0.325,2.9) 17(-0.975,2.9) 18(-1.625,2.9) 19(-2.275,2.9)
L_D_LDFL011742VV_V0E
  round 3.3 hole 1.9: 1(-4.5,-10) 2(-4.5,10) 3(4.5,-10) 4(4.5,10)
L_D_TXN40H_10221
  oval 4.3x6.6 hole 2.3x4.6: 1(0,0) 2(23,0)
L_S_ACT1210
  rect 1.05x0.6 smd: 1(-1.525,0.5) 2(-1.525,-0.5) 3(1.525,-0.5) 4(1.525,0.5)
L_S_LQW15
  custom 0.113x0.113 smd: 1(-0.475,0) 2(0.475,0)
L_S_MBKK1608
  rect 0.55x1 smd: 1(-0.625,0) 2(0.625,0)
LED_S_1608_AC
  custom 0.2x0.2 smd: A(-0.8,0) C(0.8,0)
Q_S_SOT_23F_GSD
  custom 0.2x0.2 smd: D(0,1.05) G(-0.95,-1.05) S(0.95,-1.05)
R_D_RCR60_9_5X3_5
  round 2 hole 1: 1(-10.16,0) 2(10.16,0)
R_S_1005
  custom 0.113x0.113 smd: 1(-0.475,0) 2(0.475,0)
R_S_1608
  custom 0.2x0.2 smd: 1(-0.8,0) 2(0.8,0)
R_S_2012
  custom 0.2x0.2 smd: 1(-0.9,0) 2(0.9,0)
R_S_6432_T1_25
  custom 0.487x0.487 smd: 1(-2.725,0) 2(2.725,0)
RL_D_G6QE_1A
  round 2.2 hole 1.4: 1(-12,5.75) 2(10,5.75)
  round 2.7 hole 1.9: 3(13.8,-6.25) 4(-13.8,-6.25)
TB_D_OT_264
  oval 3.5x7 hole 1.5x5: 1(-4.4,0) 2(4.4,0)
TP_HK_3_G
  custom 0.425x0.425 smd: 1(0,0)
unnamed
  round 0.01 hole 3.5 unplated: (0,0)
unnamed#3
  round 0.01 hole 3.5 unplated: (-25,55) (-19,-49) (25,55) (26,-48.5)
unnamed#4
  round 0.01 hole 3.5 unplated: (-48,-1) (68,-1)

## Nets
5V: C14.1 C23.1 C31.1 C40.1 C56.1 C65.1 C71.1 C72.1 C77.1 C79.1 C83.1 C84.1 C86.1 C91.1 C92.1 C98.1 C104.1 C105.1 C106.1 C109.1 CN8.1 CN8.2 CN8.3 CN8.4 CT1.VCC D22.C IC1.15 IC3.15 IC5.15 IC7.15 IC10.15 IC12.15 IC13.4 IC14.3 IC14.4 IC15.8 IC16.8 IC17.4 IC18.8 IC19.20 IC20.20 LED4.A LED5.A PS9.+VOUT PS10.1 PS11.1 R19.2 R20.2 R28.2 R29.2 R38.2 R39.2 R47.2 R48.2 R62.2 R63.2 R72.2 R73.2 R82.2 R85.1 R130.2 R131.2 R132.2 R133.2 R134.2 R135.2 R136.2 R141.2 TP49.1
24V: C4.1 C10.1 C11.1 C17.1 C35.1 C50.1 C76.1 D2.C L4.1 PS1.4 PS3.1 PS5.1 PS7.1 R11.1 R12.1 R13.2 RLY2.2 TP7.1 TP48.1 ZD1.C
+5V_AC: C80.1 C81.1 C82.1 C85.1 D23.C IC15.1 PS10.7 R86.2 TP54.1
+5V_DC: C90.1 C96.1 C101.1 C102.1 C103.1 D24.C D25.C IC16.1 IC18.1 PS11.7 R129.2 TP63.1
+14V_M: C53.1 C57.1 C58.1 C66.1 C67.1 IC9.1 IC10.5 IC12.5 R57.2 TP33.1
+14V_N: C32.1 C33.1 C38.1 C41.1 C42.1 IC5.5 IC6.1 IC7.5 R43.2 TP27.1
+14V_P: C15.1 C16.1 C21.1 C24.1 C25.1 IC1.5 IC2.1 IC3.5 R22.2 TP17.1
GND: C14.2 C23.2 C31.2 C40.2 C56.2 C65.2 C71.2 C72.2 C74.2 C75.2 C77.2 C78.2 C79.2 C83.2 C84.2 C86.2 C91.2 C92.2 C95.1 C98.2 C100.1 C104.2 C105.2 C106.2 C107.2 C108.2 C109.2 CN7.2 CN8.5 CN8.6 CN8.7 CN8.8 CN8.11 CN8.12 CN8.15 CN8.16 CN8.19 CN8.20 CN8.23 CN8.24 CN8.31 CN8.32 CN8.39 CN8.40 CN8.50 CN8.59 CN8.60 CT1.GND D22.A IC1.9 IC1.16 IC3.9 IC3.16 IC5.9 IC5.16 IC7.9 IC7.16 IC10.9 IC10.16 IC12.9 IC12.16 IC13.11 IC14.2 IC17.11 IC19.1 IC19.9 IC19.10 IC19.19 IC20.1 IC20.3 IC20.4 IC20.5 IC20.6 IC20.7 IC20.8 IC20.9 IC20.10 IC20.19 L8.1 L9.1 L10.1 LED3.C PC2.3 PS9.-VOUT PS10.2 PS11.2 R15.2 R84.1 R113.1 R126.1 TP43.1 TP50.1 TP56.1 TP65.1
GND_5VAC: C80.2 C81.2 C82.2 C85.2 IC15.4 PS10.5 R86.1 R97.2 TP55.1
GND_5VDC: C90.2 C96.2 C101.2 C102.2 C103.2 IC16.4 IC18.4 PS11.5 R111.2 R127.2 R129.1 TP64.1
GND_24V: C4.2 C10.2 C11.2 C17.2 C35.2 C50.2 C76.2 LED1.C PS1.3 PS3.2 PS5.2 PS7.2 PS9.-VIN Q2.S R17.1 TP9.1 TP53.1 ZD1.A
GND_M: C51.2 C52.2 C53.2 C57.2 C58.2 C59.2 C60.2 C66.2 C67.2 C68.1 C69.2 CN5.G1 CN5.G2 CN6.G1 CN6.G2 D18.A D20.A IC9.3 IC9.4 IC10.1 IC10.3 IC10.8 IC12.1 IC12.3 IC12.8 PS7.5 Q7.S Q8.S R60.1 R67.1 R74.2 TP37.1
GND_N: C32.2 C33.2 C34.2 C36.2 C37.2 C38.2 C39.2 C41.2 C42.2 C43.1 CN3.G1 CN3.G2 CN4.G1 CN4.G2 D13.A IC5.1 IC5.3 IC5.8 IC6.3 IC6.4 IC7.1 IC7.2 IC7.3 IC7.8 PS5.5 Q5.S Q6.S1 Q6.S2 Q6.S3 R42.1 R46.1 R49.2 TP28.1
GND_P: C15.2 C16.2 C18.2 C19.2 C20.2 C21.2 C22.2 C24.2 C25.2 C26.1 CN1.G1 CN1.G2 CN2.G1 CN2.G2 D8.A IC1.1 IC1.3 IC1.8 IC2.3 IC2.4 IC3.1 IC3.2 IC3.3 IC3.8 PS3.5 Q3.S Q4.S1 Q4.S2 Q4.S3 R26.1 R27.1 R30.2 TP19.1
/DI0_BO: CN8.51 R139.2
/DI1_BO: CN8.52 R140.2
/DO1_BI: CN8.42 IC20.2 R141.1
/DO3_BI: CN8.44 IC19.6 R133.1
/FLT: C108.1 IC1.13 IC3.13 IC5.13 IC7.13 IC10.13 IC12.13 IC19.8 R135.1 TP67.1
/MAINRLY_24V: D2.A Q2.D R12.2 RLY2.1 TP11.1
/PWM1A_BI: CN8.25 IC19.2 R136.1
/PWM1B_BI: CN8.26 IC19.3 R130.1
/PWM2A_BI: CN8.27 IC19.4 R131.1
/PWM2B_BI: CN8.28 IC19.5 R132.1
/PWM_MA: IC10.11 IC19.17 R62.1 TP69.1
/PWM_MB: IC12.11 IC19.16 R72.1 TP70.1
/PWM_N: IC5.11 IC7.11 IC19.15 R38.1 R47.1 TP71.1
/PWM_P: IC1.11 IC3.11 IC19.18 R19.1 R28.1 TP68.1
/RESET: IC1.14 IC3.14 IC5.14 IC7.14 IC10.14 IC12.14 IC19.14 TP72.1
AC_L: C6.1 C7.1 D7.A D12.C R4.2 R5.2 RLY2.3 TP2.1
AC_L_IN: C3.1 C120.1 L2.2 PS1.2 R1.1 R2.1 R88.1 RLY2.4 TP10.1
AC_N: C87.2 CT1.8 CT1.9 CT1.10 L3.1 L5.2 R94.1 R100.1
AC_N_IN: C3.2 C6.2 C7.2 C121.1 CT1.1 CT1.2 CT1.3 L2.4 PS1.1 TP8.1
AD0: C88.2 CN8.9 IC17.14 R96.2 TP58.1
AD1: CN8.10 IC13.8 IC13.9 TP47.1
AD2: C70.2 CN8.13 IC13.14 R79.2 TP46.1
AD4: C94.2 CN8.17 IC17.1 R108.2 TP59.1
AD6: C97.2 CN8.21 IC17.7 R124.2 TP62.1
FG: C8.2 C9.2 C120.2 C121.2 C122.2 C123.2 CAM1.1 TB3.1 TB3.2
MAINRLY_5V: IC20.18 R14.1 TP74.1
RDY: C107.1 IC1.12 IC3.12 IC5.12 IC7.12 IC10.12 IC12.12 IC19.7 R134.1 TP66.1
SIG1: C2.1 C122.1 F1.2 L1.4 R3.2 ZNR1.1
SIG2: C2.2 C123.1 L1.2 R3.1 TB2.1 TB2.2 ZNR1.2
VDC_M: D6.A D14.C D27.C D28.C L3.2 Q4.D1 Q4.D2 Q4.D3 Q4.D4 Q5.D Q7.D
VDC_M_DCT: C48.2 C49.2 C54.1 C55.1 C110.2 C111.1 C112.2 C113.1 C114.2 C115.1 D29.C Q8.D R56.1 R61.2 R102.1
VDC_N: C54.2 C55.2 C93.2 C99.2 C111.2 C113.2 C115.2 D12.A D14.A L6.2 L7.2 Q6.D1 Q6.D2 Q6.D3 Q6.D4 R61.1 R110.1 R114.1 R122.1 R128.1 TB5.1 TB5.2
VDC_P: C48.1 C49.1 C110.1 C112.1 C114.1 D6.C D7.C D26.C Q3.D R56.2 R117.1 TB4.1 TB4.2
VREF: C78.1 IC14.5 IC17.10 TP51.1
VREF_IN: C73.2 C89.1 IC17.8 IC17.9 R81.2 R99.1
N18160714: C20.1 D8.C IC1.2 R18.1
N18160718: D4.A R18.2
N18160720: D4.C D26.A
N18160890: C18.1 C19.1 IC2.8 PS3.7
N18160918: IC1.10 R20.1
N18160932: C22.1 CN1.S D5.A IC1.7 Q3.G R21.2 R26.2 TP18.1
N18160934: IC2.7 R25.1 R27.2
N18160956: IC1.6 R21.1 R23.1
N18161146: R22.1 R24.1
N18161536: IC3.10 R29.1
N18161570: C26.2 CN2.S D9.A IC3.7 Q4.G R30.1 R31.2 TP22.1
N18161621: IC3.6 R31.1 R32.1
N18162020: C39.1 D13.C IC5.2 R37.1
N18162024: D10.A R37.2
N18162026: D10.C D27.A
N18162137: IC5.10 R39.1
N18162177: C34.1 CN3.S D11.A IC5.7 Q5.G R40.2 R42.2 TP26.1
N18162199: IC5.6 R40.1 R41.1
N18162278: D11.C R41.2
N18162297: C36.1 C37.1 IC6.8 PS5.7
N18162335: IC6.7 R45.1 R46.2
N18162845: IC7.10 R48.1
N18162894: C43.2 CN4.S D15.A IC7.7 Q6.G R49.1 R50.2 TP31.1
N18162939: IC7.6 R50.1 R51.1
N18165597: C93.1 L6.1 R101.1 R106.2 R110.2
N18165601: D24.A IC16.2 L6.4 R101.2 TP60.1
N18165829: IC16.3 L6.3 R111.1 R114.2
N18166226: C99.1 L7.1 R115.1 R122.2 R125.2
N18166230: D25.A IC18.2 L7.4 R115.2 TP61.1
N18166390: R117.2 R118.1
N18166392: R118.2 R119.1
N18166394: R119.2 R120.1
N18166396: R120.2 R121.1
N18166398: R121.2 R125.1
N18166467: IC18.3 L7.3 R127.1 R128.2
N18172539: LED3.A R85.2
N18174546: C51.1 C52.1 IC9.8 PS7.7
N18174588: IC9.7 R59.1 R60.2
N18174803: C68.2 CN6.S D19.A IC12.7 Q8.G R74.1 R75.2 TP42.1
N18174813: C59.1 CN5.S D17.A IC10.7 Q7.G R65.2 R67.2 TP36.1
N18174987: C60.1 D18.C IC10.2 R64.1
N18174991: D16.A R64.2
N18175001: D16.C D28.A
N18175042: IC10.10 R63.1
N18175086: IC10.6 R65.1 R66.1
N18175142: D17.C R66.2
N18175684: IC12.10 R73.1
N18175726: IC12.6 R75.1 R76.1
N18175764: D19.C R76.2
N18175788: C69.1 D20.C IC12.2 R77.1
N18175855: D21.A R77.2
N18175865: D21.C D29.A
N18186220: IC19.13 R137.1 R139.1
N18186262: IC19.12 R138.1 R140.1
N18188625: F1.1 TB1.1 TB1.2
N18188823: C8.1 L1.3 L2.1
N18188901: C9.1 L1.1 L2.3
N18189364: LED1.A R11.2
N18189573: PC2.6 R13.1
N18189577: PC2.1 R14.2 R15.1 TP12.1
N18189655: PC2.4 Q2.G R17.2
N18196094: R43.1 R44.1
N18196224: R44.2 R45.2
N18196230: R24.2 R25.2
N18197780: R58.2 R59.2
N18197809: R57.1 R58.1
N18259366: LED4.C R137.2
N18259444: LED5.C R138.2
N18316829: C70.1 IC13.13 R78.2 R79.1
N18316863: IC13.1 IC13.2 R78.1
N18316907: IC13.6 IC13.7 R80.1
N18316911: C73.1 IC13.12 R80.2 R81.1
N18317049: CT1.VO IC13.5 TP44.1
N18317051: CT1.VREF IC13.3 TP45.1
N18317079: C74.1 D22.C/A IC13.10 R83.1
N18317089: C75.1 CN7.1 R82.1 R83.2 R84.2
N18318229: IC16.7 R112.1
N18318249: IC16.6 R107.1
N18318251: C94.1 IC17.2 R107.2 R108.1
N18318261: IC16.5 L9.2
N18318275: C95.2 IC17.3 R112.2 R113.2
N18318401: C88.1 IC17.13 R95.2 R96.1
N18318429: C100.2 IC17.5 R116.2 R126.2
N18318435: C97.1 IC17.6 R123.2 R124.1
N18318510: IC18.7 R116.1
N18318530: IC18.6 R123.1
N18318540: IC18.5 L10.2
N18485742: L4.2 PS9.+VIN
N18577271: C87.1 L5.1 R87.1 R93.2 R94.2
N18577275: D23.A IC15.2 L5.4 R87.2 TP57.1
N18577437: IC15.7 R98.1
N18577464: IC15.3 L5.3 R97.1 R100.2
N18577468: IC15.6 R95.1
N18578861: C89.2 IC17.12 R98.2 R99.2
N18580990: IC14.1 TP52.1
N18591595: R103.2 R104.1
N18591939: R102.2 R109.1
N18591941: R103.1 R109.2
N18592249: R88.2 R89.1
N18592251: R89.2 R90.1
N18592253: R90.2 R91.1
N18592255: R91.2 R92.1
N18592257: R92.2 R93.1
N18593903: R104.2 R105.1
N18593990: R105.2 R106.1
N18876199: R1.2 R4.1
N18876231: R2.2 R5.1
N18995776: IC15.5 L8.2
N181610561: D5.C R23.2
N181616991: D9.C R32.2
N181630051: D15.C R51.2

Pads without a net: CN7 NC1 NC2; CN8 14 18 22 29 30 33 34 35 36 37 38 41 43 45 46 47 48 49 53 54 55 56 57 58; IC1 4; IC2 2 5 6; IC3 4; IC5 4; IC6 2 5 6; IC7 4; IC9 2 5 6; IC10 4; IC12 4; IC19 11; IC20 11 12 13 14 15 16 17; PS3 6; PS5 6; PS7 6; PS9 NC NC2 RC

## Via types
v1: diameter 0.6, hole 0.3, TOP to BOTTOM, 140 vias
v2: diameter 1, hole 0.5, TOP to BOTTOM, 372 vias
v3: diameter 1.4, hole 0.8, TOP to BOTTOM, 6 vias

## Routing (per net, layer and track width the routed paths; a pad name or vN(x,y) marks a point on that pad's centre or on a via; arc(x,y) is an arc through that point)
5V: length 157.4
  TOP w0.2: 181.2,29.95 v1(181.2,28.95) ; 181.05,30.1 179.75,30.1 ; 124.5,33.4 124.5,32.82 ; 191.35,30.1 192.65,30.1 ; 159.6,30.15 v1(159.6,29) ; 287.45,20 v1(288.75,20) ; 192.8,29.95 v1(192.8,28.95)
  TOP w0.25: CN8.3 224.25,5.9 v2(223.45,5.1) ; 203.47,30.1 204.73,30.1 ; 204.9,29.93 v1(204.9,28.95) ; 98.8,42.67 98.8,43.3 v1(97.6,44.5) 96.7,44.5 96.5,44.7 D22.C ; v2(223.8,13) 224.1,12.48 224.2,12.38 224.25,12.3 CN8.4 ; 158.17,30.3 159.43,30.3
  TOP w0.3: 206.69,161.3 207.81,161.3 ; 292.3,19.81 292.3,18.36 292.65,18.01 293.36,18.01 ; 178.8,18.59 178.8,19.81 ; v1(94.65,59.3) C72.1 ; v1(205.1,161.4) 205.45,161.3 R72.2 ; v2(260.3,33.2) 259.4,33.4 C98.1 ; TP49.1 100.6,41.5 99.6,42.5 98.99,42.5 ; 178.8,16.99 178.8,18.21 ; IC13.4 93.8,58.36 ; 173.41,15.2 v1(172,15.2) ; 283.16,27.5 282.1,27.5 ; 178.63,21.6 v1(177.5,21.6) ; 187.69,161.8 v1(188.85,161.8) ; 173.48,21.6 v1(172.4,21.6) ; C71.1 90.54,65.3 90.64,65.4 90.64,66.88 ; 90.53,63.84 v1(90.53,63.1) ; 178.8,20.19 178.8,21.41 ; v2(292.3,21.6) 292.3,20.19 ; v2(270.1,31.3) 271.21,31.3 ; 185.33,161.8 v1(184.2,161.8) ; 271.31,33.4 271.4,32.5 271.4,31.49 ; 173.6,20.19 173.6,21.41
  TOP w0.35: IC17.4 260.5,30.8 260.3,31 260.3,31.59 ; LED4.A 188,11.6 v1(187.2,12.4) 188,13.2 LED5.A ; v2(260.3,33.2) 260.3,32.01
  TOP w0.4: 164.7,33.27 164.7,30.42 v2(164.4,29.9) ; 185.7,33.27 v2(185.7,31.9) ; 121.22,31.6 121.7,31.6 122.3,31 v2(123,31) 123,32.47 ; 185.7,33.73 185.68,34.21 185.68,35.39 ; 124.5,32.7 123.23,32.7 ; 124.5,32.7 124.5,32.82 ; 124.5,32.7 127.1,32.7 127.43,32.74 PS10.1 ; v2(199.45,31.75) 199.7,32.3 199.7,33.27 ; v2(210.3,31.9) 210.7,32.3 210.7,33.38 ; 281.9,25.8 C105.1 283,26.4 282.6,26.8
  TOP w0.45: C71.1 90.53,63.84 ; C83.1 124.5,33.4 ; C104.1 283.16,27.5 ; 93.8,58.36 C72.1
  TOP w0.5: 210.7,33.77 210.7,34.4 211.18,34.88 211.18,35.6 ; IC19.20 195.34,22.01 195.62,22.3 C106.1 ; C56.1 180.82,158.9 180.82,158.03 ; 199.7,33.77 199.7,34.58 199.68,34.6 199.68,35.47 ; v2(197.88,22.3) 196.78,22.3 ; C65.1 201.32,158.75 201.32,157.96 ; 223.56,11.69 223.56,12.51 v2(223.8,13) ; 111.3,30.84 v2(111.3,32.05) ; IC14.4 IC14.3 243.4,24.55 C79.1 ; IC15.8 121,33.3 121,31.88 ; 164.68,35.35 164.68,34.42 164.7,34.4 C40.1 ; v2(241,24.6) 242.22,24.6 ; 223.56,6.31 223.56,5.95 223.53,5.69 v2(223.45,5.1) ; IC20.20 293.36,18.01 ; C98.1 IC18.8 ; 201.3,160.25 v2(201.3,161.45) ; 180.8,160.15 v2(180.8,161.45)
  TOP w0.6: CN8.1 223.56,6.31 ; CN8.2 223.56,11.69 ; 164.68,35.35 IC7.15 ; IC3.15 199.68,35.47 ; IC1.15 211.18,35.6 ; IC5.15 185.68,35.39 ; IC12.15 201.32,157.96 ; IC10.15 180.82,158.03
  TOP w0.8: 199.7,33.77 C23.1 199.7,33.27 ; 242.22,24.6 C79.1 ; 121,31.88 C86.1 121.22,31.6 ; 210.7,33.77 C14.1 210.7,33.38 ; 98.99,42.5 R82.2 98.8,42.67 ; 173.48,21.6 R133.2 173.6,21.41 ; 185.7,33.27 C31.1 185.7,33.73 ; 271.4,31.49 C91.1 271.21,31.3 ; C65.1 201.3,160.25 ; 123,32.47 C84.1 123.23,32.7 ; 292.3,20.19 C109.1 292.3,19.81 ; 192.65,30.1 R28.2 192.8,29.95 ; R135.2 173.41,15.2 ; C56.1 180.8,160.15 ; R62.2 185.33,161.8 ; C40.1 164.7,33.27 ; R134.2 173.6,20.19 ; 159.6,30.15 R47.2 159.43,30.3 ; R85.1 111.3,30.84 ; 181.05,30.1 R38.2 181.2,29.95 ; 179.75,30.1 R39.2 ; R29.2 191.35,30.1 ; R63.2 187.69,161.8 ; 178.8,20.19 R130.2 178.8,19.81 ; R132.2 178.8,16.99 ; 204.73,30.1 R19.2 204.9,29.93 ; 260.3,31.59 C92.1 260.3,32.01 ; R72.2 206.69,161.3 ; 196.78,22.3 C106.1 ; 178.63,21.6 R136.2 178.8,21.41 ; R20.2 203.47,30.1 ; R141.2 287.45,20 ; 207.81,161.3 R73.2 ; R48.2 158.17,30.3 ; 178.8,18.21 R131.2 178.8,18.59
  TOP w1: 94,28.08 v2(94,26.6) ; 281.42,28 281.42,29.39 281.5,29.78 281.71,30.09 PS11.1
  TOP w1.2: C77.1 94,28.08
  TOP w1.5: 271.31,33.4 IC16.8 ; CT1.VCC 90.64,66.88
  CONDUCTIVE3 w0.8: PS10.1 130.2,32.88 ; PS10.1 128.5,31.18 ; PS10.1 126.8,32.88 ; CT1.VCC 90.64,65.7 ; PS11.1 282,31.88 ; PS11.1 283.5,33.1 ; PS11.1 283.5,30.2 ; PS11.1 285.7,31.88
  CONDUCTIVE3 w1: PS9.+VOUT 102,25.61 ; PS9.+VOUT 102,28.01 ; PS9.+VOUT 103.7,26.81 ; PS9.+VOUT 100.3,26.81
  vias: v2(124.5,23.5) v2(126,23.5) v2(127.5,23.5) v2(133.5,12.5) v2(135,12.5) v2(136.5,12.5) v2(279.7,31.4) v2(279.7,29.6) v2(281.4,28)
24V: length 107.9
  TOP w0.4: R11.1 72.3,12.7 ; C10.1 72.3,15.5
  TOP w0.5: C76.1 88.2,16.6 ; C76.1 92.2,16.6 ; C76.1 90.2,17.95 ; 122.85,159.5 125.33,159.5 R13.2 ; 103.22,161.4 106.7,161.4 107,161.1 107,159.47 ; 102.95,161.12 102.95,160.05 102.69,159.79 R12.1 ; 93.47,17.85 L4.1 92.45,16.6 ; TP7.1 89.4,20.7 ; TP7.1 86.2,20.7 ; TP7.1 87.8,18.75 ; TP7.1 87.8,22.65 ; 107.12,159.2 108.2,159.2 108.55,159.04 v2(109.1,158.8)
  TOP w0.6: 83.5,16.9 v2(83.5,18.5) 83.5,18.6 ; 83.5,16.9 85.2,16.9 ; 83.5,16.9 C11.1 ; 83.5,16.9 81.8,16.9 ; 145.1,26.8 v2(145.2,26.8) ; ZD1.C 74.4,14.95 ; ZD1.C 76.9,17.2 ; ZD1.C 79.5,14.95 ; PS5.1 140.9,32.88 ; PS5.1 142.5,31.28 ; PS5.1 144.1,32.88
  TOP w0.8: 103.22,161.4 D2.C 102.95,161.12 ; RLY2.2 108.35,155.75 107,157.1 C4.1 ; 107,159.47 C4.1 ; C4.1 107.12,159.2 ; R13.2 v2(125.7,157.8) 126.6,156.9 126.6,155.65
  TOP w1: PS3.1 234.22,32.1 231.17,32.1 ; C50.1 126.6,153.38 127.48,152.5 PS7.1 ; C17.1 v2(227.7,32.1)
  TOP w1.2: C50.1 126.6,155.65 ; C35.1 145.2,28.5 ; C17.1 231.17,32.1
  TOP w1.7: TP48.1 122.85,159.5
  CONDUCTIVE3 w0.6: PS3.1 236.5,32.88 ; PS3.1 235,31.38 ; PS3.1 233.5,32.88
  CONDUCTIVE3 w0.8: PS1.4 81.3,45.26 ; PS1.4 79.46,47.7 ; PS1.4 79.46,43.25 ; PS1.4 77.45,45.26 ; PS5.1 143.95,32.88 ; PS5.1 141.15,32.88 ; PS5.1 142.5,34.2 ; PS5.1 142.5,30.75
  CONDUCTIVE3 w1: PS7.1 127.48,151.3 ; PS7.1 127.48,147.9 ; PS7.1 125.78,149.6 ; RLY2.2 113,155.75 ; RLY2.2 111,157.75 ; RLY2.2 111,153.75 ; RLY2.2 109,155.75
  vias: v2(71.9,17.1) v2(76.95,17.73) v2(90.21,22.71) v2(90.25,18.58) v2(92.6,18.5) v2(145.22,30.19) v2(145.18,28.47)
+5V_AC: length 27.6
  TOP w0.2: 128.8,51.8 127.75,51.8
  TOP w0.3: v2(127,54.8) 126.2,54 TP54.1
  TOP w0.45: C82.1 128.8,51.8
  TOP w0.5: 124.2,45.17 v2(124.2,43.4) ; 128.6,53.48 128.6,54.52 ; 128.32,54.8 v2(127,54.8) ; 122.12,45.4 121.08,45.4 ; D23.C R86.2 ; C85.1 IC15.1
  TOP w0.6: 127.62,51.8 127.62,52.22 C80.1 ; 127.62,51.8 127.62,49 PS10.7 ; 127.62,51.8 127.75,51.8
  TOP w0.8: D23.C 124.2,45.17 ; R86.2 122.12,45.4 ; 128.32,54.8 C81.1 128.6,54.52 ; C80.1 128.6,53.48 ; 121.08,45.4 C85.1
  CONDUCTIVE3 w0.8: PS10.7 128.5,49.82 ; PS10.7 130.2,48.12 ; PS10.7 128.5,46.42 ; PS10.7 126.8,48.12
+5V_DC: length 53.6
  TOP w0.2: 279.2,45.1 279.2,46.08
  TOP w0.3: IC18.1 258.05,43.3 259.15,44.4 D25.C
  TOP w0.4: 272.35,44.52 272.35,43.39 IC16.1
  TOP w0.45: C103.1 279.2,45.1
  TOP w0.5: v2(260.9,41.5) 259.77,41.5 ; 259.23,41.5 257.66,41.5 IC18.1 ; C102.1 278.4,46.2 279.2,46.2 ; 279.2,46.2 279.2,46.08 ; 279.2,46.2 282.58,46.2 PS11.7 291.5,47.12 292,46.62 292,45.58 ; 298,51.72 298,49.4 293.9,45.3 292.27,45.3 ; D24.C 273.05,45.4 274.2,45.4 ; 277.32,45.4 276.27,45.4 ; 276,45.67 v2(276,47) ; 275.73,45.4 274.68,45.4
  TOP w0.8: 292,45.58 R129.2 292.27,45.3 ; D24.C 272.35,44.52 ; 276.27,45.4 C101.1 ; C101.1 276,45.67 ; C101.1 275.73,45.4 ; 259.77,41.5 C96.1 259.23,41.5 ; 274.2,45.4 C90.1 274.68,45.4 ; C102.1 277.32,45.4
  TOP w1.7: TP63.1 298,51.72
  CONDUCTIVE3 w0.8: PS11.7 281.6,47.12 ; PS11.7 285.6,47.12 ; PS11.7 283.5,48.7 ; PS11.7 283.5,45.3
+14V_M: length 24.6
  TOP w0.4: 205.2,144.73 205.2,146.24 205.13,146.3 205.13,146.99 ; 184.63,146.89 184.63,146.34 184.4,146.1 184.4,144.83
  TOP w0.5: C57.1 185.3,143.7 C58.1 ; C67.1 206.1,144.5 C66.1 ; 207.1,142.85 v2(207.1,141.3) ; 159.9,143.45 159.9,144.68 v2(160.2,145.2) ; 159.55,143.1 158.91,142.31 158.8,142.2 R57.2 ; v2(186.3,141.5) 186.3,142.82
  TOP w0.6: v2(160.2,145.2) 160.7,145.2 161.2,145.7 C53.1 160.5,146.5 159.91,147.09 IC9.1 ; IC10.5 184.63,146.89 ; IC12.5 205.13,146.99
  TOP w0.8: 205.2,144.73 C67.1 ; 184.4,144.83 C58.1
  TOP w1.2: C66.1 207.1,142.85 ; 186.3,142.82 C57.1
  TOP w1.7: 159.55,143.1 TP33.1 159.9,143.45
+14V_N: length 26.4
  TOP w0.3: 158.31,55.49 158.31,56.11 159,56.8 C38.1
  TOP w0.5: C38.1 158.1,57.49 157.33,57.49 ; 181.87,46.39 181.87,47.06 182.9,48.1 182.9,48.73 ; 182,50.4 181,50.4 ; 182,50.4 v2(182.6,50.4) ; 182,50.4 C32.1 ; 181.57,49 182.62,49 ; IC7.5 160.87,46.56 162.2,47.9 162.2,48.73 ; 159.22,57.6 v2(160.4,57.6) ; C41.1 161.2,49 162.18,49
  TOP w0.6: IC6.1 157.33,57.49 ; IC5.5 181.87,46.39
  TOP w0.7: 160.4,50.45 160.4,51.5 v2(159.8,52.1)
  TOP w0.8: C38.1 159.22,57.6 ; 182.9,48.73 C33.1 182.62,49 ; 162.2,48.73 C42.1 162.18,49 ; 158.31,55.49 R43.2 ; 180.9,49 181.57,49
  TOP w1.2: C41.1 160.4,50.45
  BOTTOM w0.5: v2(160.4,57.6) 157.55,57.6
  BOTTOM w1.7: 157.55,57.6 TP27.1
+14V_P: length 25.7
  TOP w0.3: 227.79,55.4 228.59,54.6 R22.2
  TOP w0.5: 227.6,54.23 227.6,54.59 227.3,54.89 227.3,55.37 ; 207.37,46.39 207.37,46.97 208.2,47.8 208.2,49.73 ; C16.1 207.5,50 ; 207.5,50 206.5,50 ; 207.5,50 C15.1 ; C25.1 196.2,49.5 196.9,50.2 196.9,50.85
  TOP w0.6: 197.24,51.5 v2(198.5,51.5) ; IC3.5 195.87,46.9 196.2,47.23 196.2,48.68 ; IC1.5 207.37,46.39 ; IC2.1 227.6,54.23
  TOP w0.8: 196.2,48.68 C25.1 ; 208.2,49.73 C16.1 ; v2(206.4,52.5) C15.1 ; v2(227,56.7) 227.3,56.18 C21.1 ; 227.3,55.37 C21.1 ; C21.1 227.79,55.4
  TOP w1.2: 196.9,50.85 C24.1 197.24,51.5
  BOTTOM w0.5: 228.95,57.1 227.95,56.92 v2(227,56.7)
  BOTTOM w1.7: 228.95,57.1 TP17.1
GND: length 615.8
  TOP w0.2: v1(226.93,3.88) 227.25,4.2 227.25,6.02 ; 124.5,34.54 124.5,35.15 v2(123.95,35.7) ; v1(229.5,4.7) 229.5,3.9 229.1,3.5 228.5,3.5 228.1,3.9 228.1,4.45 228.25,4.6 228.25,6.02 ; 225.25,11.94 225.25,12.3 225.23,12.41 v2(225.15,13) 224.75,12.6 224.75,11.98 ; 91.7,44.2 92,44.2 ; 92,44.2 91.7,43.9 ; 92,44.2 92.5,44.2 ; 92,44.2 91.7,44.5 ; 92,45.3 91.7,45 ; 92,45.3 91.8,45.5 ; 92,45.3 92.5,45.3 ; 92,45.3 91.7,45.3 ; 285.2,27.5 284.4,27.5
  TOP w0.25: D22.A v1(95.5,43.8) ; CN8.40 233.25,12.25 232.85,12.65 v1(232.85,13.5) ; CN8.31 231.25,5.2 231.4,5.05 v2(232.25,5.05) 233.11,5.05 233.25,5.19 CN8.39 ; v1(235.5,13) 235.75,12.75 CN8.50 ; CN8.24 229.25,12.4 v2(228.71,13.02) 228.25,12.4 CN8.20 ; CN8.15 227.25,6.02 ; CN8.23 229.25,5.2 v1(229.5,4.7) ; v1(258.3,15.1) 255.48,15.1 255.2,15.38 255.2,19.61 253.21,21.6 229.56,21.6 224.06,27.1 202.64,27.1 v1(202.34,27.3) 202.04,27.1 v1(156.9,27.1) 152.07,22.27 134.47,22.27 129.74,27 119.7,27 118.8,27.9 118.8,31.8 v2(119.4,32.4) ; v2(113.19,32.55) 114.7,32.55 115.2,32.05 115.2,29.1 118.6,25.7 128.85,25.7 133.82,20.73 153.32,20.73 v1(157.9,25.3) 203.7,25.3 v1(204.2,24.8) 204.7,25.3 223.67,25.3 228.77,20.2 252.3,20.2 v1(253.5,19) 253.5,15.1 255.4,13.2 v1(260.7,13.2) ; CN8.6 224.75,11.98 ; CN8.11 226.25,4.75 225.8,4.3 225.13,4.3 v2(224.53,4.2) 224.7,5.4 ; CN8.19 228.25,6.02 ; CN8.16 227.25,12.2 227.16,12.43 v2(226.95,12.99) 226.25,12.1 CN8.12 ; 224.7,5.4 225,5.4 225.25,5.65 CN8.7 ; 224.7,5.4 224.7,5.57 224.75,5.7 CN8.5 ; CN8.8 225.25,11.94 ; CN8.32 v1(231.25,13.4)
  TOP w0.3: IC20.4 286.5,15.97 ; 258.41,31.8 v2(257,31.8) 256.62,32.17 255.66,32.17 ; v1(295.6,17.57) 295.3,17.27 IC20.19 ; L9.1 265.5,31.8 265.7,31.6 v1(265.7,30.6) 265.04,30.6 ; 91.7,45.3 91.7,43.7 v2(92.1,42.9) ; IC20.8 286.5,13.38 ; 261.9,31.61 261.9,30.61 R113.1 ; v1(259.7,28.9) R126.1 259.6,30.7 259.2,31.1 C98.2 ; v1(93.95,49.75) 93.84,50.09 93.8,50.2 IC13.11 ; v1(91.47,64.9) 91.47,64.16 ; IC17.11 260.5,18.8 v2(260.3,17.9) ; IC20.9 286.5,12.72 ; IC20.3 286.15,16.62 ; IC20.7 286.5,14.03 ; C108.2 172.7,16.8 172.4,17.1 v1(172.4,17.6) 172.4,18.1 172.7,18.4 C107.2 ; v1(93.8,60.25) 93.8,59.62 ; IC20.5 286.5,15.32 ; IC20.6 286.5,14.68
  TOP w0.35: v2(185.5,16.3) 186.2,16.73 IC19.9 ; 196.31,20.7 195.4,20.7 194.82,21.27 IC19.19
  TOP w0.4: 238.44,11.9 v1(238.44,13) ; v2(238.44,5.2) 238.44,5.25 ; v2(151.8,15) 151.45,15
  TOP w0.45: C83.2 124.5,34.54 ; 93.8,59.62 C72.2 ; 91.47,64.16 C71.2 ; R84.1 92.5,44.2 ; C95.1 265.04,30.6 ; 284.4,27.5 C104.2 ; 255.66,32.17 C100.1 ; C75.2 92.5,45.3
  TOP w0.5: IC7.9 157.06,37.98 ; IC7.9 157.06,34.53 ; IC7.9 155.98,36.26 ; 238.44,9.45 CN8.60 239.5,11.1 ; 213.52,36.26 IC1.16 212.44,37.98 ; 242.22,26.2 v2(241,26.2) ; C91.2 272.55,29.7 ; C91.2 270.25,29.7 ; C91.2 271.4,28.55 ; 289.55,18.01 IC20.1 288.1,19.02 ; TP50.1 101.9,37.5 ; TP50.1 105.1,37.5 ; TP50.1 103.5,39.45 ; TP50.1 103.5,35.55 ; C77.2 96,31.4 ; C77.2 92,31.4 ; C77.2 94,32.75 ; IC5.9 176.98,36.26 ; IC5.9 178.06,37.98 ; IC5.9 178.06,34.53 ; C84.2 123,35.45 ; 178.05,160 C56.2 179.56,158.9 179.56,158.03 ; 238.44,8.55 CN8.59 239.5,6.9 ; IC3.9 190.98,36.26 ; IC3.9 192.06,34.78 ; IC3.9 192.06,37.98 ; 208.94,155.53 IC12.9 210.02,157.25 ; 196.71,20.7 v2(197.88,20.7) ; 179.2,160.25 v2(179.2,161.45) ; C65.2 199.7,159 ; C65.2 198.55,160 ; C65.2 199.7,161.15 ; IC12.16 200.06,158.8 ; IC12.16 198.98,157.25 ; IC12.16 200.06,155.53 ; v2(189.45,160.06) 188.44,159.05 188.44,158.11 ; C86.2 122.2,30 ; C86.2 121,28.85 ; C86.2 119.85,30 ; TP65.1 289,28.6 ; TP65.1 287.05,27 ; TP65.1 290.95,27 ; TP65.1 289,25.4 ; IC20.10 289.55,11.99 ; IC20.10 286.65,11.99 ; IC20.10 288.1,10.97 ; IC1.9 203.56,37.98 ; IC1.9 202.48,36.26 ; IC1.9 203.56,34.6 ; C40.2 166.3,34.5 ; C40.2 167.45,33.5 ; C40.2 166.3,32.35 ; TP43.1 149.5,16.6 ; TP43.1 149.5,13.4 ; TP43.1 147.55,15 ; IC3.16 200.94,34.7 ; IC3.16 202.02,36.26 ; IC3.16 200.94,37.98 ; IC7.16 167.02,36.26 ; IC7.16 165.94,34.7 ; IC7.16 165.94,37.98 ; IC19.10 186.3,15.99 v2(185.5,16.3) ; IC5.16 186.94,37.98 ; IC5.16 188.02,36.26 ; IC5.16 186.94,34.7 ; C23.2 201.3,34.5 ; C23.2 201.3,32.35 ; C23.2 202.45,33.5 ; 113.2,31.75 LED3.C 114.35,30.6 ; C14.2 213.45,33.5 ; C14.2 212.3,32.35 ; C14.2 212.3,34.5 ; 92.1,38.6 CN7.2 90.85,40.8 ; 188.44,155.53 IC10.9 189.52,157.25 ; C78.2 249,23.7 ; C78.2 250.15,24.7 ; C78.2 248,24.7 ; C109.2 290.7,18.85 ; R15.2 137.5,161.45 ; L10.1 245.65,33.6 ; C105.2 286.1,25.8 ; PC2.3 135.65,161.92 ; TP56.1 171,159.4 ; TP56.1 172.95,161 ; TP56.1 169.05,161 ; TP56.1 171,162.6 ; C92.2 261.9,32.95 ; IC14.2 243.7,25.5 243.2,26 C79.2 ; 212.44,35.52 212.44,34.7 ; 208.94,158.06 208.94,159.15 v2(209.7,159.9) ; C31.2 187.3,32.35 ; C31.2 188.45,33.5 ; C31.2 187.3,34.5 ; 178.48,157.25 IC10.16 179.56,155.53 ; v2(185.6,22.51) 186.1,22.01 IC19.1 ; 110.72,34.6 109.75,34.6 ; 290.7,20.27 v2(290.7,21.6) ; 238.44,5.25 238.44,6.1 ; 151.45,15 149.81,15 ; C74.2 91.15,46.8
  TOP w0.6: IC12.9 208.94,158.06 ; IC10.9 188.44,158.11 ; IC1.16 212.44,35.52 ; CN8.59 238.44,6.1 ; CN8.60 238.44,11.9 ; IC10.16 179.56,158.03
  TOP w0.8: 196.71,20.7 C106.2 196.31,20.7 ; C79.2 242.22,26.2 ; 261.9,31.61 C92.2 ; C56.2 179.2,160.25 ; C98.2 258.41,31.8 ; C109.2 290.7,20.27
  TOP w1: v2(286.47,28.55) 286.47,31.45 PS11.2 ; v2(92.1,42.9) CN7.2
  TOP w1.5: 126.35,35.42 PS10.2 130.65,35.42
  TOP w1.7: 149.81,15 TP43.1
  CONDUCTIVE2 w0.8: CT1.GND 92.55,65.43 ; 126.8,35.42 PS10.2 130.2,35.42
  CONDUCTIVE2 w1: PS9.-VOUT 103.7,29.35 ; PS9.-VOUT 102,30.55 ; PS9.-VOUT 100.3,29.35 ; PS9.-VOUT 102,28.15 ; 285.3,34.42 PS11.2 281.7,34.42
  BOTTOM w0.8: 130.3,35.42 PS10.2 126.7,35.42
  BOTTOM w1: 100.2,29.35 PS9.-VOUT 103.8,29.35 ; 285.4,34.42 PS11.2 281.6,34.42
  BOTTOM w1.5: CT1.GND 92.55,65
  vias: v1(232.7,23.5) v1(245.7,34.2) v1(245.7,27.5) v1(248,23.7) v1(250.7,25.2) v1(251.6,31.9) v1(254,27) v1(263.7,21) v1(264.7,15.4) v1(268.5,32) v1(274.9,25.2) v1(275.5,34.2) v2(88.5,41.5) v2(88.5,30.5) v2(89.4,51) v2(90.5,61.6) v2(94,33.4) v2(98,24) v2(100.5,37.5) v2(101,62) v2(101,50.5) v2(101,45.5) v2(110,24) v2(122,23.5) v2(122.3,29) v2(127.9,29) v2(133.9,25.8) v2(134.5,3) v2(136.2,35.4) v2(137.9,162.3) v2(141,16) v2(146.5,162) v2(152.5,27) v2(155.5,3.5) v2(156,17.5) v2(156.5,29.9) v2(157.5,162) v2(166,29.9) v2(167.5,161) v2(172.8,156.7) v2(178.06,30.15) v2(180.5,9.5) v2(186.5,3.5) v2(187.4,31.9) v2(189.56,30.2) v2(191.7,156.9) v2(197.3,157) v2(199.7,161.45) v2(201.1,31.8) v2(201.95,30.1) v2(211.7,20.6) v2(211.8,31.9) v2(216.8,162.95) v2(217,158.5) v2(218,3) v2(223.5,35) v2(223.9,19) v2(227.1,26.2) v2(233,3) v2(246.5,11.5) v2(249.19,31.4) v2(258.5,3) v2(261.9,33.2) v2(268.1,26.8) v2(271,8) v2(272.9,29.7) v2(282.5,18) v2(285.02,29.09) v2(286.04,11.27) v2(286.05,16.16) v2(286.06,13.81) v2(286.44,26.91) v2(292,34.5) v2(294,3) v2(297,31) v2(298.5,26) v2(304,38) v2(307,15) v2(307.5,111) v2(307.5,95.5) v2(307.5,78.5) v2(307.5,63.5) v2(307.5,50) v2(307.5,39.5) v2(319.5,162) v2(325.5,151) v2(325.5,135.5) v2(325.5,117.5)
